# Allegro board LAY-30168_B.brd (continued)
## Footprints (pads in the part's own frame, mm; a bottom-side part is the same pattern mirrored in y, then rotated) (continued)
HDR205_50_TH
  rect 1.016x1.016 hole 0.66: 1(0,0)
  round 1.016 hole 0.66: 2(0,1.27) 3(1.27,0) 4(1.27,1.27) 5(2.54,0) 6(2.54,1.27) 7(3.81,0) 8(3.81,1.27) 9(5.08,0) 10(5.08,1.27)
HDR_2X10M_100_TH
  rect 1.778x1.778 hole 1.143: 1(0,0)
  round 1.778 hole 1.143: 2(2.54,0) 3(0,-2.54) 4(2.54,-2.54) 5(0,-5.08) 6(2.54,-5.08) 7(0,-7.62) 8(2.54,-7.62) 9(0,-10.16) 10(2.54,-10.16) 11(0,-12.7) 12(2.54,-12.7) 13(0,-15.24) 14(2.54,-15.24) 15(0,-17.78) 16(2.54,-17.78) 17(0,-20.32) 18(2.54,-20.32) 19(0,-22.86) 20(2.54,-22.86)
IND4_4P7X3P4_SMT
  rect 1.372x0.914 smd: 1(-2.275,1.25) 2(-2.275,-1.25) 3(2.275,-1.25) 4(2.275,1.25)
IND4_CHOKE_0805
  rect 0.914x0.406 smd: 1(-0.85,-0.4) 2(0.85,-0.4) 3(0.85,0.4) 4(-0.85,0.4)
IND_1608
  rect 0.61x0.813 smd: 1(-0.7,0) 2(0.7,0)
IND_4020
  rect 1.118x3.708 smd: 1(-1.5,0) 2(1.5,0)
IND_VLS4012E
  rect 1.549x4.013 smd: 1(-1.475,0) 2(1.475,0)
LED_0603
  rect 0.838x0.787 smd: A(-0.775,0) C(0.775,0)
LED_DUAL_3025MM_SM
  rect 1.702x1.118 smd: 1(-1.35,-0.85) 2(1.35,-0.85) 3(-1.35,0.85) 4(1.35,0.85)
MIC_WM-63PR
  rect 1.27x1.27 hole 0.762: 1(0,0)
  round 1.27 hole 0.762: 2(0,1.9)
MICROPAK_6P
  rect 0.305x0.508 smd: 1(-0.508,-0.381) 2(0,-0.381) 3(0.508,-0.381) 4(0.508,0.381) 5(0,0.381) 6(-0.508,0.381)
MLP6_2X2MM_SLUG
  rect 0.483x0.406 smd: 1(-0.913,0.65) 2(-0.913,0) 3(-0.913,-0.65) 4(0.913,-0.65) 5(0.913,0) 6(0.913,0.65)
  rect 1.016x0.991 smd: 7(0,0.3)
  rect 0.66x0.406 smd: 8(0,-0.65)
MODULE_TOUCH_PANEL_46P
  rect 2.007x2.997 smd: (-35.23,11.683) (-12.65,11.683) (23.91,11.481) (29.49,11.481)
  rect 0.279x1.245 smd: A1(-33.69,14.008) A2(-33.19,14.008) A3(-32.69,14.008) A4(-32.19,14.008) A5(-31.69,14.008) A6(-31.19,14.008) A7(-30.69,14.008) A8(-30.19,14.008) A9(-29.69,14.008) A10(-29.19,14.008) A11(-28.69,14.008) A12(-28.19,14.008) A13(-27.69,14.008) A14(-27.19,14.008) A15(-26.69,14.008) A16(-26.19,14.008) A17(-25.69,14.008) A18(-25.19,14.008) A19(-24.69,14.008) A20(-24.19,14.008) A21(-23.69,14.008) A22(-23.19,14.008) A23(-22.69,14.008) A24(-22.19,14.008) A25(-21.69,14.008) A26(-21.19,14.008) A27(-20.69,14.008) A28(-20.19,14.008) A29(-19.69,14.008) A30(-19.19,14.008) A31(-18.69,14.008) A32(-18.19,14.008) A33(-17.69,14.008) A34(-17.19,14.008) A35(-16.69,14.008) A36(-16.19,14.008) A37(-15.69,14.008) A38(-15.19,14.008) A39(-14.69,14.008) A40(-14.19,14.008)
  rect 0.305x1.245 smd: B1(25.45,13.806) B2(25.95,13.806) B3(26.45,13.806) B4(26.95,13.806) B5(27.45,13.806) B6(27.95,13.806)
PBGA24_1_6X8MM
  round 0.33 smd: A2(-1,2) A3(0,2) A4(1,2) A5(2,2) B1(-2,1) B2(-1,1) B3(0,1) B4(1,1) B5(2,1) C1(-2,0) C2(-1,0) C3(0,0) C4(1,0) C5(2,0) D1(-2,-1) D2(-1,-1) D3(0,-1) D4(1,-1) D5(2,-1) E1(-2,-2) E2(-1,-2) E3(0,-2) E4(1,-2) E5(2,-2)
QFN5X3_0P5_3X3
  rect 0.813x0.305 smd: 1(-1.275,1) 2(-1.275,0.5) 3(-1.275,0) 4(-1.275,-0.5) 5(-1.275,-1) 9(1.275,-1) 10(1.275,-0.5) 11(1.275,0) 12(1.275,0.5) 13(1.275,1)
  rect 0.305x0.813 smd: 6(-0.5,-1.275) 7(0,-1.275) 8(0.5,-1.275) 14(0.5,1.275) 15(0,1.275) 16(-0.5,1.275)
QFN32_0P5_EP3P3
  oval 0.864x0.279 smd: 1(-2.45,1.75) 8(-2.45,-1.75) 17(2.45,-1.75) 24(2.45,1.75)
  rect 0.864x0.279 smd: 2(-2.45,1.25) 3(-2.45,0.75) 4(-2.45,0.25) 5(-2.45,-0.25) 6(-2.45,-0.75) 7(-2.45,-1.25) 18(2.45,-1.25) 19(2.45,-0.75) 20(2.45,-0.25) 21(2.45,0.25) 22(2.45,0.75) 23(2.45,1.25)
  oval 0.279x0.864 smd: 9(-1.75,-2.45) 16(1.75,-2.45) 25(1.75,2.45) 32(-1.75,2.45)
  rect 0.279x0.864 smd: 10(-1.25,-2.45) 11(-0.75,-2.45) 12(-0.25,-2.45) 13(0.25,-2.45) 14(0.75,-2.45) 15(1.25,-2.45) 26(1.25,2.45) 27(0.75,2.45) 28(0.25,2.45) 29(-0.25,2.45) 30(-0.75,2.45) 31(-1.25,2.45)
  rect 3.302x3.302 smd: 33(0,0)
QFN32_S142EP
  custom 0.07x0.07 smd: 1(-2.4,1.751) 2(-2.4,1.251) 3(-2.4,0.751) 4(-2.4,0.25) 5(-2.4,-0.25) 6(-2.4,-0.751) 7(-2.4,-1.251) 8(-2.4,-1.751) 9(-1.751,-2.4) 10(-1.251,-2.4) 11(-0.751,-2.4) 12(-0.25,-2.4) 13(0.25,-2.4) 14(0.751,-2.4) 15(1.251,-2.4) 16(1.751,-2.4) 17(2.4,-1.751) 18(2.4,-1.251) 19(2.4,-0.751) 20(2.4,-0.25) 21(2.4,0.25) 22(2.4,0.751) 23(2.4,1.251) 24(2.4,1.751) 25(1.751,2.4) 26(1.251,2.4) 27(0.751,2.4) 28(0.25,2.4) 29(-0.25,2.4) 30(-0.751,2.4) 31(-1.251,2.4) 32(-1.751,2.4)
  rect 3.607x3.607 smd: 33(0,0)
RC0402_25
  round 0.635 smd: 1(-0.508,0) 2(0.508,0)
RC0603_OV
  oval 0.889x1.143 smd: 1(-0.762,0) 2(0.762,0)
RC0805_OV
  oval 0.889x1.524 smd: 1(-0.965,0) 2(0.965,0)
SC-70
  rect 0.381x0.813 smd: 1(-0.66,-1.079) 2(0,-1.079) 3(0.66,-1.079) 4(0.66,1.079) 5(-0.66,1.079)
SC_75
  rect 0.483x0.635 smd: 1(-0.5,-0.647) 2(0.5,-0.647) 3(0,0.647)
SLP1616P6
  rect 0.305x0.635 smd: 1(-0.5,-0.76) 2(0,-0.76) 3(0.5,-0.76) 4(0.5,0.76) 5(0,0.76) 6(-0.5,0.76)
  rect 1.295x0.457 smd: 7(0,0)
SO8-25X75-200
  oval 0.635x1.905 smd: 1(-1.905,-3.67) 2(-0.635,-3.67) 3(0.635,-3.67) 4(1.905,-3.67) 5(1.905,3.67) 6(0.635,3.67) 7(-0.635,3.67) 8(-1.905,3.67)
SO8_1P27_4X5
  rect 1.6x0.61 smd: 1(-2.7,1.905) 2(-2.7,0.635) 3(-2.7,-0.635) 4(-2.7,-1.905) 5(2.7,-1.905) 6(2.7,-0.635) 7(2.7,0.635) 8(2.7,1.905)
SOD523
  rect 0.61x0.813 smd: A(0.85,0) C(-0.85,0)
SOD-123
  rect 1.321x1.219 smd: A(-1.626,0) C(1.626,0)
SOD_523_1P4
  rect 0.406x0.406 smd: A(0.7,0) C(-0.7,0)
SOT23-3-1P95
  rect 0.584x1.194 smd: 1(-0.953,-1.25) 2(0.953,-1.25) 3(0,1.25)
SOT23-5_A
  rect 1.016x0.762 smd: 1(-1.3,0.95) 2(-1.3,0) 3(-1.3,-0.95) 4(1.3,-0.95) 5(1.3,0.95)
SOT23_6_B
  rect 0.61x1.194 smd: 1(-0.95,-1.2) 2(0,-1.2) 3(0.95,-1.2) 4(0.95,1.2) 5(0,1.2) 6(-0.95,1.2)
SOT23_A
  rect 0.787x0.889 smd: 1(-0.94,-1.003) 2(0.94,-1.003) 3(0,1.003)
SOT23_S6
  rect 1.27x0.635 smd: 1(-1.219,0.94) 2(-1.219,0) 3(-1.219,-0.94) 4(1.219,-0.94) 5(1.219,0) 6(1.219,0.94)
SOT143B
  rect 0.991x0.61 smd: 1(-0.75,-1)
  rect 0.508x0.61 smd: 2(0.95,-1) 3(0.95,1) 4(-0.95,1)
SOT323_3
  rect 0.406x0.991 smd: 1(0.65,-1.06) 2(-0.65,-1.06) 3(0,1.06)
SOT-23
  rect 1.016x1.397 smd: 1(-0.95,-1.1) 2(0.95,-1.1) 3(0,1.1)
SOT-363_0P65_SMT
  rect 0.762x0.381 smd: 1(-1.085,0.65) 2(-1.085,0) 3(-1.085,-0.65) 4(1.085,-0.65) 5(1.085,0) 6(1.085,0.65)
SOT_143
  rect 1.219x1.397 smd: 1(-0.75,-1.1)
  rect 1.016x1.397 smd: 2(0.95,-1.1) 3(0.95,1.1) 4(-0.95,1.1)
SPACER_139T
  round 5.588 hole 3.531: 1(0,0)
SSOP8_DCU
  rect 0.279x1.219 smd: 1(-0.75,-1.499) 2(-0.25,-1.499) 3(0.25,-1.499) 4(0.75,-1.499) 5(0.75,1.499) 6(0.25,1.499) 7(-0.25,1.499) 8(-0.75,1.499)
SW4_PB_ESW_SM_P177
  rect 1.397x2.794 smd: 1(2.248,4.547) 2(2.248,-4.547) 3(-2.248,4.547) 4(-2.248,-4.547)
SW6_DPDT_11X6MM
  rect 1.143x1.143 hole 0.711: 1(0,0)
  round 1.143 hole 0.711: 2(2,0) 3(4,0) 4(0,-2.5) 5(2,-2.5) 6(4,-2.5)
TESTPOINT_35MIL
  round 0.889 smd: 1(0,0)
TP_TH_063
  round 2.311 hole 1.6: 1(0,0)
TPAD_030
  round 0.762 smd: 1(0,0)
TSOT23_8_0P65_2X1
  rect 1.219x0.432 smd: 1(-1.31,0.975) 2(-1.31,0.325) 3(-1.31,-0.325) 4(-1.31,-0.975) 5(1.31,-0.975) 6(1.31,-0.325) 7(1.31,0.325) 8(1.31,0.975)
TSSOP8_A
  rect 1.448x0.457 smd: 1(-2.15,0.975) 2(-2.15,0.325) 3(-2.15,-0.325) 4(-2.15,-0.975) 5(2.15,-0.975) 6(2.15,-0.325) 7(2.15,0.325) 8(2.15,0.975)
VFBGA54_8X8
  round 0.356 smd: A1(-3.2,3.2) A2(-2.4,3.2) A3(-1.6,3.2) A7(1.6,3.2) A8(2.4,3.2) A9(3.2,3.2) B1(-3.2,2.4) B2(-2.4,2.4) B3(-1.6,2.4) B7(1.6,2.4) B8(2.4,2.4) B9(3.2,2.4) C1(-3.2,1.6) C2(-2.4,1.6) C3(-1.6,1.6) C7(1.6,1.6) C8(2.4,1.6) C9(3.2,1.6) D1(-3.2,0.8) D2(-2.4,0.8) D3(-1.6,0.8) D7(1.6,0.8) D8(2.4,0.8) D9(3.2,0.8) E1(-3.2,0) E2(-2.4,0) E3(-1.6,0) E7(1.6,0) E8(2.4,0) E9(3.2,0) F1(-3.2,-0.8) F2(-2.4,-0.8) F3(-1.6,-0.8) F7(1.6,-0.8) F8(2.4,-0.8) F9(3.2,-0.8) G1(-3.2,-1.6) G2(-2.4,-1.6) G3(-1.6,-1.6) G7(1.6,-1.6) G8(2.4,-1.6) G9(3.2,-1.6) H1(-3.2,-2.4) H2(-2.4,-2.4) H3(-1.6,-2.4) H7(1.6,-2.4) H8(2.4,-2.4) H9(3.2,-2.4) J1(-3.2,-3.2) J2(-2.4,-3.2) J3(-1.6,-3.2) J7(1.6,-3.2) J8(2.4,-3.2) J9(3.2,-3.2)
WLCSP4_0P4_0P8X0P8_SMDP
  round 0.254 smd: A1(-0.2,0.2) A2(0.2,0.2) B1(-0.2,-0.2) B2(0.2,-0.2)
WLCSP12_0P4_1P38X1P68MM_SMDP
  round 0.254 smd: A1(-0.4,0.6) A2(0,0.6) A3(0.4,0.6) B1(-0.4,0.2) B2(0,0.2) B3(0.4,0.2) C1(-0.4,-0.2) C2(0,-0.2) C3(0.4,-0.2) D1(-0.4,-0.6) D2(0,-0.6) D3(0.4,-0.6)
XFMR6_6P6X6P2
  rect 1.194x1.295 smd: (-2.73,0) (2.73,0) 1(-2.73,2.54) 3(-2.73,-2.54) 4(2.73,-2.54) 6(2.73,2.54)
XQFN8_1P45X1P25MM
  rect 0.787x0.203 smd: 1(-0.75,0)
  rect 0.203x0.711 smd: 2(-0.4,-0.65) 3(0,-0.65) 4(0.4,-0.65) 6(0.4,0.65) 7(0,0.65) 8(-0.4,0.65)
  rect 0.711x0.203 smd: 5(0.75,0)
XTAL2-3P2X1P5-SM
  rect 1.092x1.905 smd: 1(-1.25,0) 2(1.25,0)
XTL2_11P6X4P85_SM
  rect 5.588x2.032 smd: 1(-4.75,0) 2(4.75,0)
XTLOSC4_3P2X2P5MM_SM
  rect 1.397x1.194 smd: 1(-1.1,-0.8) 2(1.1,-0.8) 3(1.1,0.8) 4(-1.1,0.8)

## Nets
5V_SDA_PSW: C241.1 R352.1 U31.C2(VBUS1) U31.D1(VBUS2) U31.D2(VBUS3)
5V_SYS: C50.1 C51.1 C61.1 C62.1 D14.A J1.2(B1) J1.4(B2) J1.6(B3) J1.8(B4) J25.8 R7.1 R33.1 R64.1 R85.1 R95.1 R328.1 R336.1 U4.1(IN) U4.3(S\H\D\N\) U6.1(IN)
5V_USB_HS: C84.1 C97.1 C239.1 L7.2 U1.P6(USB_OTG2_VBUS) U35.C2(VBUS1) U35.D1(VBUS2) U35.D2(VBUS3)
5V_USB_OTG: C79.1 C93.1 C240.1 J1.3(A2) L4.2 U1.N6(USB_OTG1_VBUS) U34.C2(VBUS1) U34.D1(VBUS2) U34.D2(VBUS3)
GND: C1.2 C2.2 C3.2 C4.2 C6.2 C7.2 C8.2 C9.2 C10.2 C11.2 C12.2 C13.2 C14.2 C15.2 C16.2 C17.2 C18.2 C19.2 C20.2 C21.2 C22.2 C23.2 C24.2 C25.2 C26.2 C27.2 C29.2 C30.2 C31.2 C32.2 C33.2 C34.2 C35.2 C36.2 C37.2 C39.2 C40.2 C41.2 C42.2 C43.2 C44.2 C45.2 C46.2 C47.2 C48.2 C49.2 C50.2 C51.2 C52.2 C53.2 C54.2 C55.2 C56.2 C57.2 C58.2 C59.2 C61.2 C62.2 C63.2 C64.2 C65.2 C66.2 C67.2 C68.2 C69.2 C70.2 C71.2 C72.2 C73.2 C74.2 C75.2 C76.2 C77.2 C78.2 C79.2 C80.2 C81.2 C82.2 C83.2 C84.2 C85.2 C86.2 C87.2 C88.2 C89.2 C90.2 C91.2 C92.2 C93.2 C97.2 C98.2 C99.2 C100.2 C101.1 C102.2 C103.2 C104.2 C105.2 C106.2 C107.2 C108.2 C109.2 C110.2 C111.2 C112.2 C113.2 C114.1 C115.2 C116.2 C117.2 C118.1 C119.2 C120.2 C121.1 C127.2 C128.2 C129.2 C130.2 C133.2 C134.1 C135.1 C136.2 C137.2 C138.2 C140.2 C141.2 C142.2 C143.2 C144.2 C145.2 C146.2 C147.2 C148.2 C149.2 C150.2 C160.2 C161.2 C162.2 C163.2 C164.2 C165.2 C166.2 C167.2 C168.2 C169.2 C170.2 C171.2 C184.2 C185.2 C186.2 C187.2 C188.2 C189.2 C190.2 C191.2 C192.2 C193.2 C194.2 C195.2 C196.2 C197.2 C198.2 C199.2 C200.2 C201.2 C202.2 C203.2 C204.2 C205.2 C206.2 C207.2 C208.2 C209.2 C210.2 C211.2 C212.2 C213.2 C214.2 C215.2 C216.2 C217.2 C218.2 C219.2 C220.2 C221.2 C222.2 C223.2 C229.2 C234.2 C235.2 C236.2 C237.2 C238.2 C239.2 C240.2 C241.2 C242.2 C243.2 C244.2 C245.2 C246.2 C247.2 C248.2 C249.2 C252.2 C254.2 C255.2 C257.2 C258.2 C259.2 C260.2 C261.2 C262.2 C263.2 C264.2 C265.2 C266.2 C267.2 C268.2 C270.2 C272.2 C273.2 C274.2 C275.2 C276.2 C277.2 C278.2 D1.A(ANODE) D3.4(CATHODE2) D11.3(ANODES) D20.C(CATHODE) H1.1(NC_1) H2.1(NC_1) H3.1(NC_1) H4.1(NC_1) J1.9(A5) J1.10(B5) J2.2 J2.3 J6.1 J8.A3(GND2) J8.A5(R0) J8.A6(R1) J8.A7(R2) J8.A13(G0) J8.A14(G1) J8.A21(B0) J8.A22(B1) J8.A23(B2) J8.A29(GND3) J8.A36(GND4) J8.B6(GND1) J9.5(P5) J10.5(P5) J11.2 J12.1 J19.10(CHS_GND) J21.4 J21.6 J21.8 J21.10 J21.12 J21.14 J21.16 J21.18 J21.20 J24.7 J25.6 J25.7 J34.3(A2) J34.5(A3) J35.1 J35.2 J35.10 J39.6(VSS) J39.SH1(GND1) J39.SH2(GND2) J39.SH3(GND3) J39.SH4(GND4) J41.5(P5) J42.1 L6.2 L9.2 L14.1 L17.2 L22.2 Q1.3(G) Q4.2(SOURCE) Q15.1(SOURCE) R11.2 R30.2 R31.2 R39.2 R45.2 R52.2 R54.2 R65.2 R66.2 R97.1 R103.2 R113.1 R116.2 R117.2 R125.2 R133.2 R135.2 R136.2 R137.2 R140.2 R141.2 R143.2 R146.2 R148.2 R149.2 R150.2 R152.2 R172.2 R173.2 R180.2 R181.2 R182.2 R185.2 R214.2 R247.1 R248.1 R249.1 R250.1 R251.1 R252.1 R253.1 R254.1 R255.1 R256.1 R257.1 R258.1 R259.1 R260.1 R266.2 R267.2 R269.2 R303.2 R304.2 R314.2 R326.2 R333.2 R335.2 R342.2 R348.2 R351.2 R377.2 R380.1 R387.1 R389.2 R391.2 R414.2 SW1.3(NO1) SW1.6(NO2) SW2.1(A1) SW2.2(A2) SW3.1(A1) SW3.2(A2) SW8.1(A1) SW8.2(A2) SW9.1(A1) SW9.2(A2) T1.4 TP2.1 TP3.1 TP4.1 TP5.1 TVS1.1(A1) TVS2.1(A1) TVS3.1(A1) TVS4.1(A1) TVS5.1(A1) U1.A1(VSS1) U1.A14(VSS2) U1.B5(VSS3) U1.B10(VSS4) U1.E2(VSS5) U1.E13(VSS6) U1.G7(VSS7) U1.G8(VSS8) U1.H7(VSS9) U1.H8(VSS10) U1.J7(VSS11) U1.J8(VSS12) U1.K2(VSS13) U1.K6(TEST_MODE) U1.K9(NGND_KEL0) U1.K13(VSS14) U1.L9(VSS15) U1.N1(DCDC_GND_1) U1.N2(DCDC_GND_2) U1.N5(VSS16) U1.N8(VSS17) U1.P1(VSS18) U1.P14(VSS19) U2.1(GND) U3.4(PGND) U3.6(AGND) U4.2(GND) U5.1(GND) U6.2(GND) U7.1(GND) U8.2(GND) U9.7(GND) U11.7(GND) U12.2(GND) U13.9(DGND) U13.20(SPKGND2) U13.24(SPKGND1) U13.28(AGND) U13.33(GND_PADDLE) U14.2(GND) U15.3(GND) U16.1(GND) U16.33(PADDLE) U17.2(A2) U19.B3(VSS) U19.C1(VSSQ1) U19.E5(VSSQ2) U20.A1(VSS1) U20.A3(VSSQ1) U20.B7(VSSQ2) U20.C3(VSSQ3) U20.D7(VSSQ4) U20.E3(VSS2) U20.J1(VSS3) U31.B3(GND1) U31.C3(GND2) U31.D3(GND3) U32.3(RSVD1) U32.5(GND1) U32.12(GND2) U32.13(RSVD2) U33.4(GND) U34.B3(GND1) U34.C3(GND2) U34.D3(GND3) U35.B3(GND1) U35.C3(GND2) U35.D3(GND3) U37.B2(GND) U38.C2(VSSA) U38.C8(VSS1) U38.D3(USB0_VSSA_TERM) U38.D4(VSS2) U38.D5(VSS3) U38.F2(USB0_VSSA_REF) U38.G8(VSS4) U38.J3(VSS5) U38.J6(VSS6) U39.1(GND) U40.2(GND) U44.4(GND) U45.2(GND) U46.2(GND) U48.4(GND) U49.2(GND) U49.5(DIR) Y1.2(GND1) Y1.4(GND2)
P3V3_SDA: C186.1 C255.1 C260.1 C262.1 C263.1 C264.1 C265.1 C266.1 C267.1 C270.1 J34.1(A1) L24.1 R213.1 R215.1 R378.1 R381.1 R382.1 R383.1 R388.2 R390.2 R394.1 R402.2 R413.1 R418.2 R423.1 U38.B2(VDDA) U38.C5(VBAT) U38.D1(USB0_VDDA3V3_DRIVER) U38.D2(USB0_VDDA3V3) U38.F10(VDDIO1) U38.K5(VDDIO2) U40.5(OUT) U44.1(VCCA) U45.3(VCCA) U46.1(VCCA) U48.1(VCCA) U49.1(VCCA)
P5V0_SDA_USB_CONN_VBUS: J41.1(P1) L23.1 U39.4(VCC)
P5V_SDA: C184.1 C185.1 C257.1 C259.1 L23.2 R212.1 R353.1 R379.1 U31.B1(VINT1) U31.B2(VINT2) U31.C1(VINT3) U40.1(IN) U40.3(S\H\D\N\)
P5V_SDA_S: J1.5(A3) R352.2 R353.2
VDD_COIN_3V: D5.A J6.2 R16.1
VDD_HIGH_IN_3V3: C229.1 J4.1 R14.1 R310.2 R311.2
VDD_HIGH_IN_MCU: C15.1 C16.1 J4.2 R14.2 U1.P12(VDD_HIGH_IN)
VDD_SNVS_3V3: C49.1 C59.1 D4.A R34.2 R354.2 U5.4(VCC)
VDD_SNVS_IN: C23.1 J5.2 R15.2 R21.1 U1.M9(VDD_SNVS_IN)
VDD_SOC_IN: C8.1 C9.1 C10.1 C11.1 C12.1 C13.1 C14.1 C17.1 C18.1 C19.1 C20.1 J36.1 R13.1 U1.F6(VDD_SOC_IN_1) U1.F7(VDD_SOC_IN_2) U1.F8(VDD_SOC_IN_3) U1.F9(VDD_SOC_IN_4) U1.G6(VDD_SOC_IN_5) U1.G9(VDD_SOC_IN_6) U1.H6(VDD_SOC_IN_7) U1.H9(VDD_SOC_IN_8) U1.J5(DCDC_SENSE) U1.J9(VDD_SOC_IN_9)
VDD_USB_3V: C82.1 C83.1 U1.K8(VDD_USB_CAP)
VDDA_ADC_3P3_MCU: C6.1 C7.1 J3.2 R12.2 U1.N14(VDDA_ADC_3P3)
VDDA_ADC_3V3: C57.1 J3.1 R12.1 R44.2
AUD_INT: R96.1 R222.2 R275.1 R287.2 U1.H13(GPIO_AD_B1_08)
BACKLIGHT_CTL: R314.1 R344.1 U1.B14(GPIO_B1_15) U8.4(CE)
BL+: J8.A2(VBL+) R63.2
BL-: C91.1 J8.A1(VBL-) R65.1 R66.1 U8.3(FB)
BOOT0_LED: R388.1 R392.1 U38.K2(P1_1/GPIO0[8]/CTOUT_7/EMC_A6/SG)
BOOT1: R389.1 U38.K1(P1_2/GPIO0[9]/CTOUT_6/EMC_A7/SG)
BOOT2: R390.1 U38.C6(P2_8/SGPIO15/CTOUT_0/U3_DIR/EMC)
BOOT3: R391.1 U38.B10(P2_9/GPIO1[10]/CTOUT_3/U3_BAUD/)
BOOT_FLASH: J42.2 U38.C10(P2_7/GPIO0[7]/CTOUT_1/U3_UCLK/E)
CAN1_H: C101.2 D11.2(CATHODE2) FL1.1 J11.1 R87.2 R88.1
CAN1_L: C103.1 D11.1(CATHODE1) FL1.2 J11.3 R89.2 R91.2
CAN2_RX: U1.L10(GPIO_AD_B0_15) U12.4(RXD)
CAN2_TX: U1.H14(GPIO_AD_B0_14) U12.1(TXD)
CAN_STBY: R92.1 R169.1 R260.2 SW7.3(A3) U1.G14(GPIO_AD_B0_05)
CAN_VIO_3V3: C100.1 R86.1 R90.1 U12.5(VIO)
CSI_1V8: C247.1 J35.15 L20.2
CSI_D2: J35.6 R229.1
CSI_D3: J35.4 R228.1
CSI_D4: J35.3 R227.1
CSI_D5: J35.5 R226.1
CSI_D6: J35.7 R225.1
CSI_D7: J35.9 R224.1
CSI_D8: J35.11 R223.1
CSI_D9: J35.13 R222.1
CSI_HSYNC: J35.16 R221.1
CSI_MCLK: J35.12 R218.1
CSI_PIXCLK: J35.8 R217.1
CSI_PWDN: D17.C J22.7 J38.2 U1.L11(GPIO_AD_B1_02)
CSI_VSYNC: J35.18 R220.1
DC_5V_IN: C4.1 J2.1 Q1.1(D1) Q1.2(D2) Q1.5(D5) Q1.6(D6) Q1.7(D7) R1.1 R2.1 R6.1 TP1.1(PIN1)
DCDC_3V3: C69.1 C70.1 C71.1 C72.1 C73.1 C74.1 C75.1 C193.1 C194.1 C195.1 C196.1 C197.1 C198.1 C199.1 C200.1 C201.1 C202.1 C203.1 C204.1 C205.1 C206.1 C207.1 C208.1 C209.1 C210.1 C211.1 C212.1 C213.1 C214.1 C215.1 C216.1 C217.1 C218.1 C219.1 C220.1 C221.1 C222.1 C246.1 C249.1 C252.1 C268.1 C275.1 C276.1 C277.1 C278.1 D12.A J7.1 J13.2 J21.2 J24.8 J25.2 J25.4 J35.14 L18.1 L19.2 Q6.2(SOURCE) R24.1 R25.1 R27.1 R44.1 R48.1 R55.1 R57.1 R86.2 R93.1 R130.1 R174.1 R176.1 R177.1 R178.1 R179.1 R219.1 R230.1 R232.1 R234.1 R235.1 R236.1 R237.1 R238.1 R239.1 R240.1 R241.1 R242.1 R243.1 R244.1 R245.1 R246.1 R284.1 R293.1 R301.1 R311.1 R316.1 R324.1 R325.1 R332.1 R346.1 R349.1 R350.1 R354.1 R372.1 R393.1 R401.1 R411.1 R412.1 R419.2 R422.2 U1.E6(NVCC_EMC_1) U1.E9(NVCC_GPIO_1) U1.F5(NVCC_EMC_2) U1.F10(NVCC_GPIO_2) U1.J10(NVCC_GPIO_3) U37.A1(VIN) U44.8(VCCB) U45.7(VCCB) U46.6(VCCB) U48.8(VCCB) U49.6(VCCB)
DCDC_3V3_PG: C55.1 C56.1 TP8.1(TP) U3.1(PG) U6.3(S\H\D\N\)
DCDC_OUT: C36.1 C37.1 J36.2 L1.1 R13.2
ENET_3V3: C148.1 J19.1(LED_Y1) J19.12(LED_G12) L13.1 R126.1 R127.1 R128.1 R129.1 R130.2 R131.1 R132.1 R134.2 R138.2 R139.2 R142.2 R144.2 R145.2 R147.2 R151.2 R309.1 R322.2 U16.17(VDDIO)
ENET_B-CAST-OFF: R151.1 TP12.1(TP) U16.19(REF_CLK/B-CAST_OFF)
ENET_CONFIG0: R140.1 R142.1 U16.28(CONFIG0)
ENET_CONFIG1: R143.1 R144.1 U16.29(CONFIG1)
ENET_CRS_DV: R141.1 R145.1 U1.C12(GPIO_B1_06) U16.18(CRS_DV/CONFIG2)
ENET_INT: J21.13 J22.6 J50.2 R152.1 R262.2 R263.2 R309.2 R428.2 U1.G13(GPIO_AD_B0_10) U16.21(INTRP/N\A\N\D\_\T\R\E\E\)
ENET_LED0/NWAYEN: J19.2(LED_Y2) R148.1 U16.30(LED0/NWAYEN)
ENET_LED1/SPEED: J19.11(LED_G11) R149.1 U16.31(LED1/SPEED)
ENET_MDC: R132.2 U1.A7(GPIO_EMC_40) U16.12(MDC)
ENET_MDIO: R131.2 U1.C7(GPIO_EMC_41) U16.11(MDIO)
ENET_PHYAD0: R134.1 R137.1 U16.13(PHYAD0)
ENET_PHYAD1: R135.1 R138.1 U16.14(PHYAD1)
ENET_RST: D18.C(CATHODE) J21.5 J22.5 J49.2 R177.2 R323.1 U1.F14(GPIO_AD_B0_09)
ENET_RXD0: R150.1 U1.E12(GPIO_B1_04) U16.16(RXD0/DUPLEX)
ENET_RXD1: R136.1 R139.1 U1.D12(GPIO_B1_05) U16.15(RXD1/PHYAD2)
ENET_RXER: R146.1 R147.1 U1.C13(GPIO_B1_11) U16.20(RXER/ISO)
ENET_RXM: C147.1 J19.8(RD-) R129.2 U16.4(RXM) U17.3(A3)
ENET_RXP: C146.1 J19.7(RD+) R128.2 U16.5(RXP) U17.1(A1)
ENET_TX_CLK: TP25.1(TP) U1.B13(GPIO_B1_10) U16.9(XI)
ENET_TXD0: TP26.1(TP) U1.B12(GPIO_B1_07) U16.24(TXD0)
ENET_TXD1: U1.A12(GPIO_B1_08) U16.25(TXD1)
ENET_TXEN: U1.A13(GPIO_B1_09) U16.23(TXEN)
ENET_TXM: C145.1 J19.4(TD-) R127.2 U16.6(TXM) U17.4(A4)
ENET_TXP: C144.1 J19.3(TD+) R126.2 U16.7(TXP) U17.6(A6)
FLASH_VCC: C80.1 C81.1 C162.1 C163.1 C191.1 C192.1 R49.2 R168.1 R170.1 R171.1 R294.1 R301.2 R358.1 R359.1 R360.1 U1.K5(NVCC_SD1) U19.B4(VCC) U19.D1(VCCQ1) U19.E4(VCCQ2) U33.8(VCC)
FLEXSPI_CLK: R154.1 R361.1 U1.L4(GPIO_SD_B1_07)
FLEXSPI_CLK_B: U1.P2(GPIO_SD_B1_04) U19.B1(C\K\)
FLEXSPI_D0_A: R155.2 R362.1 U1.P3(GPIO_SD_B1_08)
FLEXSPI_D0_B: U1.M4(GPIO_SD_B1_03) U19.D5(DQ4)
FLEXSPI_D1_A: R156.2 R363.1 U1.N4(GPIO_SD_B1_09)
FLEXSPI_D1_B: U1.M3(GPIO_SD_B1_02) U19.E3(DQ5)
FLEXSPI_D2_A: R157.2 R364.1 U1.P4(GPIO_SD_B1_10)
FLEXSPI_D2_B: U1.M5(GPIO_SD_B1_01) U19.E2(DQ6)
FLEXSPI_D3_A: R158.2 R365.1 U1.P5(GPIO_SD_B1_11)
FLEXSPI_D3_B: U1.L5(GPIO_SD_B1_00) U19.E1(DQ7)
FLEXSPI_DQS: R366.1 U1.N3(GPIO_SD_B1_05)
FLEXSPI_SS0: R153.1 R356.1 R427.1 U1.L3(GPIO_SD_B1_06)
GPIO_AD_B0_00: R57.2 R341.1 U1.M14(GPIO_AD_B0_00)
GPIO_AD_B0_01: Q15.2(GATE) R55.2 R71.2 U1.H10(GPIO_AD_B0_01)
GPIO_AD_B0_02: J8.B2(RESET) J24.2 R329.1 U1.M11(GPIO_AD_B0_02)
GPIO_AD_B0_03: J24.1 R334.1 U1.G11(GPIO_AD_B0_03)
GPIO_AD_B0_04: R259.2 SW7.4(A4) U1.F11(GPIO_AD_B0_04)
GPIO_AD_B0_11: J8.B3(INT) J21.3 J22.3 R178.2 R261.2 R264.2 U1.G10(GPIO_AD_B0_11)
GPIO_AD_B1_00: J8.B4(SCL) J23.6 J35.20 R234.2 R270.2 R272.2 R277.2 U1.J11(GPIO_AD_B1_00) U13.17(SCLK)
GPIO_AD_B1_01: J8.B5(SDA) J23.5 J35.22 R232.2 R271.2 R273.2 R276.2 U1.K11(GPIO_AD_B1_01) U13.18(SDIN)
GPIO_AD_B1_03: D6.C J15.1 J22.8 U1.M12(GPIO_AD_B1_03)
GPIO_AD_B1_04: R217.2 R290.2 U1.L12(GPIO_AD_B1_04)
GPIO_AD_B1_05: R218.2 R291.2 U1.K12(GPIO_AD_B1_05)
GPIO_AD_B1_06: R220.2 R289.2 U1.J12(GPIO_AD_B1_06)
GPIO_AD_B1_07: R221.2 R288.2 U1.K10(GPIO_AD_B1_07)
GPIO_AD_B1_09: R102.1 R223.2 U1.M13(GPIO_AD_B1_09)
GPIO_AD_B1_10: R224.2 R285.2 U1.L13(GPIO_AD_B1_10)
GPIO_AD_B1_11: R225.2 R286.2 U1.J13(GPIO_AD_B1_11)
GPIO_AD_B1_12: R100.1 R226.2 U1.H12(GPIO_AD_B1_12)
GPIO_AD_B1_13: R101.1 R227.2 U1.H11(GPIO_AD_B1_13)
GPIO_AD_B1_14: R99.1 R228.2 U1.G12(GPIO_AD_B1_14)
GPIO_AD_B1_15: R98.1 R229.2 U1.J14(GPIO_AD_B1_15)
GPIO_B0_04: J8.A24(B3) R247.2 R325.2 U1.C8(GPIO_B0_04)
GPIO_B0_05: J8.A25(B4) R248.2 SW5.1(A1) U1.B8(GPIO_B0_05)
GPIO_B0_06: J8.A26(B5) R249.2 SW5.2(A2) U1.A8(GPIO_B0_06)
GPIO_B0_07: J8.A27(B6) R250.2 SW5.3(A3) U1.A9(GPIO_B0_07)
GPIO_B0_08: J8.A28(B7) R251.2 SW5.4(A4) U1.B9(GPIO_B0_08)
GPIO_B0_09: J8.A15(G2) R252.2 SW6.1(A1) U1.C9(GPIO_B0_09)
GPIO_B0_10: J8.A16(G3) R253.2 SW7.1(A1) U1.D9(GPIO_B0_10)
GPIO_B0_11: J8.A17(G4) R254.2 SW6.2(A2) U1.A10(GPIO_B0_11)
GPIO_B0_12: J8.A18(G5) R255.2 SW6.3(A3) U1.C10(GPIO_B0_12)
GPIO_B0_13: J8.A19(G6) R256.2 R428.1 SW7.2(A2) U1.D10(GPIO_B0_13)
GPIO_B0_14: J8.A20(G7) R257.2 SW6.4(A4) U1.E10(GPIO_B0_14)
GPIO_B0_15: J8.A8(R3) R258.2 R324.2 U1.E11(GPIO_B0_15)
GPIO_SD_B0_00: J39.3(CMD) R59.2 R280.2 U1.J4(GPIO_SD_B0_00)
GPIO_SD_B0_01_B: C245.1 J39.5(CLK) R281.2 R282.2
GPIO_SD_B0_02: J39.7(DAT0) R60.2 R279.2 U1.J1(GPIO_SD_B0_02)
GPIO_SD_B0_03: J39.8(DAT1) R278.2 U1.K1(GPIO_SD_B0_03)
HP_JD: J12.5 R94.2 R275.2 TVS3.2(A2) U13.7(RINPUT3/JD3)
HP_L: C230.1 U13.31(HP_L)
HP_MIC1N: C121.2 C123.1 U13.4(LINPUT1)
HP_MIC1P: C125.1 C127.1 U13.2(LINPUT3/JD2)
HP_R: C231.1 U13.29(HP_R)
JTAG_DACK: J21.19 R182.1
JTAG_DE: J21.17 R174.2
JTAG_MOD: R303.1 TP11.1(TP) U1.F13(GPIO_AD_B0_08)
JTAG_NSRST: D13.C J21.15 R175.2
JTAG_RESET: J44.2 U38.D10(P2_5/SGPIO14/CTIN_2/USB1_VBUS/A)
JTAG_RTCK: J21.11 R181.1
JTAG_TCK: J21.9 J48.2 R180.1 U1.F12(GPIO_AD_B0_07)
JTAG_TDI_L: U38.J10(P1_18/GPIO0[13]/U2_DIR/ENET_TXD) U48.3(2A)
JTAG_TDI_TGTMCU_BUF: J49.1 R417.2
JTAG_TDO_TGTMCU_BUF: J50.1 R422.1 U49.4(B)
JTAG_TMS: J21.7 J47.2 R176.2 U1.E14(GPIO_AD_B0_06)
JTAG_VREF: J21.1 R179.2
LCD_3V3: C85.1 C86.1 C87.1 C92.1 J8.A4(VDD2) J8.B1(VDD1) R62.2 R67.1
LCDIF_CLK: J8.A30(DCLK) U1.D7(GPIO_B0_00)
LCDIF_D12: J8.A9(R4) U1.A11(GPIO_B1_00)
LCDIF_D13: J8.A10(R5) U1.B11(GPIO_B1_01)
LCDIF_D14: J8.A11(R6) U1.C11(GPIO_B1_02)
LCDIF_D15: J8.A12(R7) U1.D11(GPIO_B1_03)
LCDIF_ENABLE: J8.A34(DE) U1.E7(GPIO_B0_01)
LCDIF_HSYNC: J8.A32(HSYNC) U1.E8(GPIO_B0_02)
LCDIF_VSYNC: J8.A33(VSYNC) U1.D8(GPIO_B0_03)
LDO_1V8: C67.1 C68.1 L20.1 R49.1 TP10.1(TP) U7.2(VOUT)
MAIN_MIC2N: C126.2 C130.1 U13.5(RINPUT1)
MAIN_MIC2P: C118.2 C122.2 U13.6(RINPUT2)
MCU_DCDC_IN: C31.1 C32.1 C33.1 C34.1 C35.1 J37.1 R32.1 R357.1 U1.K4(DCDC_IN_Q) U1.L1(DCDC_IN_1) U1.L2(DCDC_IN_2)
MCU_DCDC_IN_3V3: C223.1 J37.2 R25.2 R42.2 R357.2
MICBIAS: C112.1 R104.1 R105.1 U13.1(MICBIAS)
NVCC_SD: C63.1 C64.1 R46.1 R47.1 R59.1 R60.1 R61.1 TP9.1(TP) U6.5(OUT)
ONOFF: SW2.3(B1) SW2.4(B2) U1.M6(ONOFF)
OTG1_DN: L5.2 R68.2 U1.M8(USB_OTG1_DN)
OTG1_DP: L5.3 R69.2 U1.L8(USB_OTG1_DP)
OTG2_DN: L8.2 R83.2 U1.N7(USB_OTG2_DN)
OTG2_DP: L8.3 R84.2 U1.P7(USB_OTG2_DP)
PERI_3V3: Q6.3(DRAIN) R24.2 R62.1
PERI_PWREN: Q6.1(GATE) R31.1 U1.L7(PMIC_STBY_REQ)
PMIC_ON_REQ: R38.2 R355.1 U1.K7(PMIC_ON_REQ)
POR_B: C27.1 D7.C D13.A D21.C(CATHODE) J26.1 J43.3 R20.2 R21.2 R401.2 R410.2 U1.M7(P\O\R\) U44.7(B1)
POR_BUTTON: R43.1 R355.2 SW3.3(B1) SW3.4(B2)
POWER_EN: R216.1 U38.F7(P3_1/I2S0_TX_WS/I2S0_RX_WS/CAN0)
PWDN: D17.A J35.17 R219.2
SD0_VSELECT: Q9.2(GATE) R54.1 U1.C14(GPIO_B1_14)
SD1_CLK: C244.1 R282.1 U1.J3(GPIO_SD_B0_01)
SD1_D2: J39.1(DAT2) TP27.1(TP) U1.H2(GPIO_SD_B0_04)
SD1_D3: J39.2(CD/DAT3) R172.1 TP28.1(TP) U1.J2(GPIO_SD_B0_05)
SD_CD_SW: R320.2 U1.D13(GPIO_B1_12)
SDA_JTAG_TCLK: J34.4(B2) U38.H2(TCK/SWDCLK)
SDA_JTAG_TDI: J34.8(B4) U38.G3(TDI)
SDA_JTAG_TDO: J34.6(B3) U38.H3(TDO/SWO)
SDA_JTAG_TMS: J34.2(B1) R213.2 U38.C4(TMS/SWDIO)
SDA_RST: J34.10(B5) R423.2 U38.B4(T\R\S\T\)
SDA_RST_LED: D21.A(ANODE) R412.2
SDA_RST_TGTMCU_J_B: J44.1 R400.1 R410.1
SDA_USB_CONN_DM: J41.2(P2) R375.1 U39.2(I/O1)
SDA_USB_CONN_DP: J41.3(P3) R376.1 U39.3(I/O2)
SDA_USB_DM: R375.2 U38.E2(USB0_DM)
SDA_USB_DP: R376.2 U38.E1(USB0_DP)
SDA_USBSHIELD: J41.S1(SHLD1) J41.S2(SHLD2) J41.S3(SHLD3) J41.S4(SHLD4) L22.1
SDRAM_3V3: C164.1 C165.1 C166.1 C167.1 C168.1 C169.1 C170.1 C171.1 C243.1 L18.2 R184.1 U20.A7(VDDQ1) U20.A9(VDD1) U20.B3(VDDQ2) U20.C7(VDDQ3) U20.D3(VDDQ4) U20.E7(VDD2) U20.J9(VDD3)
SEMC_A0: U1.C2(GPIO_EMC_09) U20.H7(A0)
SEMC_A1: U1.G1(GPIO_EMC_10) U20.H8(A1)
SEMC_A2: U1.G3(GPIO_EMC_11) U20.J8(A2)
SEMC_A3: U1.H1(GPIO_EMC_12) U20.J7(A3)
SEMC_A4: U1.A6(GPIO_EMC_13) U20.J3(A4)
SEMC_A5: U1.B6(GPIO_EMC_14) U20.J2(A5)
SEMC_A6: U1.B1(GPIO_EMC_15) U20.H3(A6)
SEMC_A7: U1.A5(GPIO_EMC_16) U20.H2(A7)
SEMC_A8: U1.A4(GPIO_EMC_17) U20.H1(A8)
SEMC_A9: U1.B2(GPIO_EMC_18) U20.G3(A9)
SEMC_A10: U1.G2(GPIO_EMC_23) U20.H9(A10)
SEMC_A11: U1.B4(GPIO_EMC_19) U20.G2(A11)
SEMC_A12: U1.A3(GPIO_EMC_20) U20.G1(A12)
SEMC_BA0: U1.C1(GPIO_EMC_21) U20.G7(BA0)
SEMC_BA1: U1.F1(GPIO_EMC_22) U20.G8(BA1)
SEMC_CAS: U1.D3(GPIO_EMC_24) U20.F7(C\A\S\)
SEMC_CKE: R185.1 U1.A2(GPIO_EMC_27) U20.F3(CKE)
SEMC_CLK: R283.1 U1.B3(GPIO_EMC_26)
SEMC_CS0: R184.2 U1.E1(GPIO_EMC_29) U20.G9(C\S\)
SEMC_D0: U1.E3(GPIO_EMC_00) U20.A8(DQ0)
SEMC_D1: U1.F3(GPIO_EMC_01) U20.B9(DQ1)
SEMC_D2: U1.F4(GPIO_EMC_02) U20.B8(DQ2)
SEMC_D3: U1.G4(GPIO_EMC_03) U20.C9(DQ3)
SEMC_D4: U1.F2(GPIO_EMC_04) U20.C8(DQ4)
SEMC_D5: U1.G5(GPIO_EMC_05) U20.D9(DQ5)
SEMC_D6: U1.H5(GPIO_EMC_06) U20.D8(DQ6)
SEMC_D7: U1.H4(GPIO_EMC_07) U20.E9(DQ7)
SEMC_D8: U1.C6(GPIO_EMC_30) U20.E1(DQ8)
SEMC_D9: U1.C5(GPIO_EMC_31) U20.D2(DQ9)
SEMC_D10: U1.D5(GPIO_EMC_32) U20.D1(DQ10)
SEMC_D11: U1.C4(GPIO_EMC_33) U20.C2(DQ11)
SEMC_D12: U1.D4(GPIO_EMC_34) U20.C1(DQ12)
SEMC_D13: U1.E5(GPIO_EMC_35) U20.B2(DQ13)
SEMC_D14: U1.C3(GPIO_EMC_36) U20.B1(DQ14)
SEMC_D15: U1.E4(GPIO_EMC_37) U20.A2(DQ15)
SEMC_DM0: U1.H3(GPIO_EMC_08) U20.E8(LDQM)
SEMC_DM1: U1.D6(GPIO_EMC_38) U20.F1(UDQM)
SEMC_DQS: C76.1 U1.B7(GPIO_EMC_39)
SEMC_RAS: U1.D2(GPIO_EMC_25) U20.F8(R\A\S\)
SEMC_WE: U1.D1(GPIO_EMC_28) U20.F9(W\E\)
SENSOR_3V3: C187.1 C188.1 R261.1 R262.1 R265.1 R268.1 R270.1 R271.1 R284.2 U32.1(VDDIO) U32.14(VDD)
SPDIF_BUF: R122.1 R124.2 U15.4(Y)
SPDIF_COAX_OUT: J18.2 T2.1
SPDIF_GND_PRI: R123.2 R125.1 T2.4
SPDIF_OUT_PRI: C139.2 R123.1 T2.6
SPDIF_VCC: C133.1 C138.1 J13.1 U14.5(VCC) U15.1(OE) U15.5(VCC)
SPK_LN: R119.1 U13.23(SPK_LN)
SPK_LP: R121.1 U13.25(SPK_LP)
SPK_RN: R118.1 U13.19(SPK_RN)
SPK_RP: R120.1 U13.22(SPK_RP)
SW1_RST_B: C272.1 J43.2 SW9.3(B1) SW9.4(B2)
SWD_CLK_TGTMCU_BUF: J48.1 R416.2
SWD_DIO_TGTMCU_BUF: J47.1 R419.1 U46.4(B)
TC_SDA_USB_ID: J41.4(P4) U38.F1(USB0_ID)
TCK_SWCLK: U38.H10(P1_17/GPIO0[12]/U2_UCLK/ENET_MD) U48.2(1A)
TDO_SWO: U38.J8(P1_14/GPIO1[7]/U1_RXD/EMC_D7/T0) U49.3(A)
TMS_SWDIO: U38.K4(P1_6/GPIO1[9]/CTIN_5/E\M\C\_\W\) U46.3(A)
TMS_SWDIO_TXEN: R414.1 U38.J4(P1_5/GPIO1[8]/CTOUT_10/E\M\C\_\) U46.5(DIR)
TP_2102_A: TP29.1(PIN1) U44.3(A2)
TP_2102_B: TP30.1(PIN1) U44.6(B2)
UART1_RX_TGTMCU_BUF: J45.1 U45.8(B1)
UART1_RXD: J45.2 R411.2 U1.L14(GPIO_AD_B0_13)
UART1_TX_TGTMCU_BUF: J46.1 U45.1(B2)
UART1_TXD: J46.2 R393.2 U1.K14(GPIO_AD_B0_12)
UART_RXD_ISP: U38.G10(P2_0/SGPIO4/U0_TXD/EMC_A13/USB0) U45.5(A1)
UART_TXD_ISP: U38.G7(P2_1/SGPIO5/U0_RXD/EMC_A12/USB0) U45.4(A2)
USER_BUTTON: SW8.3(B1) SW8.4(B2) TP6.1(TP) U1.L6(WAKEUP)
VAUD_3V3: C104.1 C105.1 C106.1 C107.1 R93.2 R94.1 U13.8(DCVDD) U13.10(DBVDD) U13.32(AVDD)
VLDO_3V3: C52.1 C53.1 R34.1 R42.1 R305.1 R310.1 U4.5(OUT)
VSD_3V3: C30.1 C160.1 C161.1 C242.1 J39.4(VDD) R371.1 U37.A2(VOUT)
VTRG_FAULT_B: R215.2 U31.A2(F\A\U\L\T\) U38.A8(P3_0/I2S0_RX_SCK/I2S0_RX_MCLK/I)
WALL_OV_BASE: Q3.1(B) R5.2
WALL_OV_CTL: D1.C(CATHODE) R3.2 R5.1
WALL_OVP_LED: D2.A Q3.3(C) R10.1
WDOG_B: C60.1 U1.D14(GPIO_B1_13)
N99781517: D4.C D5.C J5.1 R15.1 R16.2
N99781633: C21.1 C22.1 U1.P8(VDD_HIGH_CAP)
N99781636: C25.1 U1.M10(VDD_SNVS_CAP)
N99781637: C24.1 C26.1 U1.P10(NVCC_PLL)
N99781670: L1.2 U1.M1(DCDC_LP_1) U1.M2(DCDC_LP_2)
N99781682: C42.1 U1.N9(RTC_XTALI) Y2.1
N99781687: C43.1 U1.P9(RTC_XTALO) Y2.2
N99781694: C40.1 R28.2 U1.N11(XTALO) Y1.1
N99781701: C39.1 R28.1 R30.1 U1.P11(XTALI) Y1.3
N99781716: C29.1 R18.2 R19.1 U2.3(VCC)
N99781728: R19.2 R20.1 U2.2(R\E\S\E\T\)
N99781740: C60.2 D9.C R45.1
N99781746: D8.A D9.A R41.1 U5.3(M\R\)
N99781747: C47.1 C48.1 J7.2 L2.2 R36.1 TP7.1(TP) U3.5(OUT)
N99781749: C54.1 R35.2 R38.1 R41.2 U3.8(EN) U5.2(R\E\S\E\T\)
N99781753: C58.1 D8.C R43.2
N99781762: C44.1 C45.1 C46.1 R33.2 R35.1 U3.2(VIN)
N99781782: R36.2 R39.1 U3.7(FB)
N99781791: L2.1 U3.3(SW)
N99808656: C77.1 C78.1 R61.2 U1.J6(NVCC_SD0)
N99815013: C140.1 C141.1 L13.2 U16.3(VDDA_3.3)
N99815680: C142.1 C143.1 U16.2(VDD_1.2)
N99815919: C149.1 J19.6(CT1)
N99815924: C150.1 J19.5(CT2)
N99816488: J19.13(SH1) J19.14(SH2) L14.2
N99820323: R133.1 U16.10(REXT)
N99825452: C108.1 C109.1 C110.1 C111.1 R95.2 U13.21(SPKVDD2) U13.26(SPKVDD1)
N99827287: C113.1 U13.27(VMID)
N99827729: R96.2 U13.15(ADCLRC/GPIO1)
N99827749: R98.2 U13.13(DACLRC)
N99827769: R99.2 U13.12(BCLK)
N99827789: R100.2 U13.16(ADCDAT)
N99827809: R101.2 U13.14(DACDAT)
N99827829: R102.2 U13.11(MCLK)
N99827958: C134.2 C232.1 J16.1 R118.2
N99827962: C136.1 C232.2 J16.2 R120.2
N99828318: C135.2 C233.1 J17.1 R119.2
N99828322: C137.1 C233.2 J17.2 R121.2
N99833003: J9.S1(SHLD1) J9.S2(SHLD2) J9.S3(SHLD3) J9.S4(SHLD4) L6.1
N99833017: J9.1(P1) L4.1 U9.6(VBUS)
N99833020: J9.4(P4) R71.1 U9.3(USB ID)
N99833038: J9.2(P2) L5.1 R68.1 U9.1(DM)
N99833040: J9.3(P3) L5.4 R69.1 U9.2(DP)
N99834989: J10.S1(SHLD1) J10.S2(SHLD2) J10.S3(SHLD3) J10.S4(SHLD4) L9.1
N99834993: J10.1(P1) L7.1 U11.6(VBUS)
N99835007: J10.2(P2) L8.1 R83.1 U11.1(DM)
N99835017: J10.3(P3) L8.4 R84.1 U11.2(DP)
N99838171: D12.C R175.1
N99842431: R114.1 R115.2 U14.1(1A)
N99842486: C139.1 R122.2
N99842500: C131.2 T1.1
N99842510: C132.1 R116.1 T1.6
N99842524: C132.2 R115.1
N99842534: R114.2 R117.1 U14.3(2A) U14.6(1Y)
N99842546: J15.2 U14.4(2Y)
N99842626: J38.1 R124.1 U15.2(A)
N99842704: J18.1 T2.3
N99903207: C230.2 L10.1 R97.2
N99903209: C231.2 L11.1 R103.1
N99903219: C115.1 J12.3 L11.2 TVS4.2(A2)
N99903223: C114.2 J12.2 L10.2 TVS2.2(A2)
N99903738: J12.4 L12.2 TVS5.2(A2)
N99904959: C123.2 R107.2 R110.1
N99904961: C125.2 C128.1 C129.1 L12.1 R110.2
N99904975: C119.1 C120.1 R104.2 R107.1
N99907436: C124.2 R112.2 R113.2
N99907447: C126.1 R109.2 R111.2 R112.1
N99907449: C122.1 R106.2 R108.2 R109.1
N99907458: C116.1 C117.1 C124.1 R105.2 R106.1
N99907542: P1.1(OUT) R108.1
N99907546: P1.2(GND) R111.1
N99909350: R268.2 R269.1 U32.7(SA0/MISO)
N99909356: R266.1 U32.16(RST)
N99909379: R273.1 U32.6(SDA/MOSI)
N99909383: R272.1 U32.4(SCL/SCLK)
N99909400: C190.1 U32.2(BYP)
N99909418: C189.1 U32.8(CRST)
N99909466: R264.1 U32.9(INT2)
N99909468: R263.1 U32.11(INT1)
N99909488: R265.2 R267.1 U32.10(SA1/C\S\)
N99912430: C89.1 C90.1 L3.2 R64.2 U8.6(VIN)
N99912683: D10.A(ANODE) L3.1 U8.1(LX)
N99912703: C88.1 D10.C(CATHODE) R63.1 U8.5(OVP)
N99917011: J25.3 J26.2
N99917059: J24.9 R276.1
N99917061: J24.10 R277.1
N99917215: D14.C J25.5
N100002783: C41.1 R32.2 U1.K3(DCDC_PSWITCH)
N100054133: Q4.1(GATE) R10.2 R11.1
N100054172: C1.1 C2.1 C3.1 J1.1(A1) JP1.2 Q2.1(D1) Q2.2(D2) Q2.5(D5) Q2.6(D6) Q2.7(D7) TVS1.2(A2)
N100054253: C5.2 D2.C Q2.3(G) R4.2 R8.1
N100054255: R8.2 R9.1
N100054257: R9.2 SW1.5(COMMON2)
N100054299: C5.1 JP1.1 Q1.4(S1) Q1.8(S2) Q2.4(S1) Q2.8(S2) Q3.2(E) R1.2 R2.2 R3.1 R4.1
N100054525: D3.3(ANODE2) R7.2
N100054552: D3.1(ANODE1) R6.2
N100054568: D3.2(CATHODE1) Q4.3(DRAIN)
N100192090: J35.19 R230.2
N100192374: J35.23 L17.1
N100226351: R246.2 SW7.5(B4)
N100226419: R245.2 SW7.6(B3)
N100226426: R244.2 SW7.7(B2)
N100226433: R243.2 SW7.8(B1)
N100226440: R242.2 SW6.5(B4)
N100226447: R241.2 SW6.6(B3)
N100226454: R240.2 SW6.7(B2)
N100226461: R239.2 SW6.8(B1)
N100226670: R238.2 SW5.5(B4)
N100226677: R237.2 SW5.6(B3)
N100226684: R236.2 SW5.7(B2)
N100226691: R235.2 SW5.8(B1)
N100290781: J8.A31(DISP) R67.2
N100350746: D6.A D7.A R27.2 R29.1
N100395820: C131.1 J14.2
N100395835: J14.1 T1.3
N100531599: C65.1 C66.1 R48.2 U7.3(VIN)
N100538650: Q9.3(DRAIN) R47.2
N100538655: Q9.1(SOURCE) R46.2 R52.1 U6.4(FB)
N100585505: J39.9(DETECT) R173.1 R313.2 R320.1
N100756566: TP22.1(TP) U1.N10(GPANAIO)
N100757315: TP23.1(TP) U1.N12(U\S\B\_\O\T\G\1\_\C\H\D\)
N100763661: J24.5 R278.1
N100763684: J24.4 R279.1
N100763722: J24.6 R280.1
N100763741: J24.3 R281.1
N100763780: R283.2 U20.F2(CLK)
N100784802: J23.1 R285.1
N100784828: J23.2 R286.1
N100784849: J22.4 R287.1
N100784872: J22.1 R288.1
N100784902: J22.2 R289.1
N100784935: J23.3 R290.1
N100784954: J23.4 R291.1
N100873109: R18.1 R293.2
N100881534: R154.2 U33.6(SCK)
N100881537: R153.2 R360.2 U33.1(C\E\)
N100881743: R155.1 U33.5(SI_IO0)
N100881750: R156.1 U33.2(SO_IO1)
N100881757: R157.1 R359.2 U33.3(W\P\_IO2)
N100881764: R158.1 R358.2 U33.7(H\O\L\D\/R\E\S\E\T\_IO3)
N100937722: R168.2 R169.2 U19.A4(R\E\S\E\T\)
N100939369: R171.2 R424.1 R425.1 R427.2
N100979684: R304.1 R305.2 U4.4(FB)
N101050998: C234.1 R322.1 R323.2 U16.32(R\S\T\)
N101100421: R313.1 R371.2 R372.2
N101108824: D18.A(ANODE) R316.2
N101139052: C235.1 C236.1 R328.2 U34.B1(VINT1) U34.B2(VINT2) U34.C1(VINT3)
N101140611: Q15.3(DRAIN) R329.2 R332.2 R333.1 U34.A1(EN)
N101140956: R334.2 R349.2 U34.A2(F\A\U\L\T\)
N101141371: R335.1 U34.A3(ILIM)
N101141743: C237.1 C238.1 R336.2 U35.B1(VINT1) U35.B2(VINT2) U35.C1(VINT3)
N101141921: R341.2 R350.2 U35.A2(F\A\U\L\T\)
N101141946: R342.1 U35.A3(ILIM)
N101142201: R344.2 R346.2 R348.1 U35.A1(EN)
N101241745: C98.1 C99.1 R85.2 U12.3(VCC)
N101242370: C102.1 R88.2 R89.1
N101242461: FL1.4 R87.1 U12.7(CANH)
N101242463: FL1.3 R91.1 U12.6(CANL)
N101242940: R90.2 R92.2 R326.1 U12.8(S)
N101351285: R294.2 R356.2 U19.C2(C\S\1\)
N101351783: C248.1 J35.21 L19.1
N101474013: R361.2 U19.B2(CK)
N101474117: R362.2 U19.D3(DQ0)
N101474142: R363.2 U19.D2(DQ1)
N101474197: R364.2 U19.C4(DQ2)
N101474201: R365.2 U19.D4(DQ3)
N101481296: R366.2 U19.C3(RWDS)
N101508071: R29.2 U37.B1(EN)
N101529304: C254.1 C258.1 C261.1 L24.2 U38.E4(VDDREG1) U38.E5(VDDREG2) U38.F4(VDDREG3)
N101531474: R377.1 R378.2 U40.4(FB)
N101535047: R379.2 U38.E3(USB0_VBUS)
N101535139: R380.2 U38.F3(USB0_RREF)
N101537312: R381.2 U38.A6(DBGEN)
N101537315: R382.2 U38.B6(R\E\S\E\T\)
N101537383: R383.2 U38.A4(WAKEUP0)
N101544777: R387.2 U38.C9(P6_11/GPIO3[7]/EMC_CKEOUT0/T2_M)
N101546218: D20.A(ANODE) R392.2
N101549401: J43.1 R394.2 R400.2 U44.2(A1)
N101549759: R402.1 U44.5(OE)
N101553401: R413.2 U45.6(OE)
N101556572: R416.1 U48.7(1B)
N101556596: R417.1 U48.6(2B)
N101557543: R418.1 U48.5(DIR)
N101571275: C273.1 U38.C1(XTAL2) Y4.2
N101571285: C274.1 U38.B1(XTAL1) Y4.1
N101599117: R351.1 U31.A3(ILIM)
N101599129: R212.2 R214.1 R216.2 U31.A1(EN)
N101616215: R424.2 U19.A3(RFU1)
N101616337: R425.2 U19.A2(R\S\T\O\)
N101616340: R426.2 U19.A5(I\N\T\)
N101658009: R170.2 R426.1

Pads without a net: J1 7; J8 A35 A37 A38 A39 A40; J10 4; J12 6; J19 9; J25 1; J34 7 9; J35 24; SW1 1 2 4; U1 N13 P13; U9 4 5; U11 3 4 5; U13 3 30; U16 8 22 26 27; U17 5; U19 B5 C5; U20 E2; U32 15; U38 A1 A2 A3 A5 A7 A9 A10 B3 B5 B7 B8 B9 C3 C7 D6 D7 D8 D9 E6 E7 E8 E9 E10 F5 F6 F8 F9 G1 G2 G4 G5 G6 G9 H1 H4 H5 H6 H7 H8 H9 J1 J2 J5 J7 J9 K3 K6 K7 K8 K9 K10

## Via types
v1: diameter 0.356, hole 0.203, TOP to BOTTOM, 130 vias
v2: diameter 0.457, hole 0.203, TOP to BOTTOM, 1544 vias

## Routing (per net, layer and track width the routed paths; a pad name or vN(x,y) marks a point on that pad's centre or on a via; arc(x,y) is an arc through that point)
5V_SDA_PSW: length 0.8
  TOP w0.254: U31.D1 U31.D2 U31.C2
5V_SYS: length 21
  TOP w0.381: J25.8 29.9,30.79 28.19,29.08 v2(27.05,29.08) D14.A ; R7.1 v2(20.95,22.73)
  BOTTOM w0.381: R85.1 76.58,20.45 77.34,19.68 77.34,15.5 v2(75.69,13.84) ; v2(20.95,22.73) 22.1,23.88 25.53,23.88
  vias: v2(28.85,21.87) v2(29.44,22.23) v2(29.44,21.59) v2(30.1,22.23) v2(33.02,39.37) v2(35.18,39.98) v2(36.07,39.98) v2(53.47,14.22) v2(53.47,13.46) v2(53.47,12.7) v2(82.68,9.53) v2(83.57,9.53) v2(86.49,18.92) v2(87.25,18.92) v2(91.31,58.17) v2(92.2,58.17) v2(93.09,58.17) v2(93.85,58.17) v2(97.28,18.54) v2(97.28,17.78) v2(97.28,17.02) v2(97.54,28.07) v2(97.54,27.05) v2(98.17,27.43) v2(98.17,26.54) v2(98.17,18.54) v2(98.17,17.78) v2(98.17,17.02)
5V_USB_HS: length 56.7
  TOP w0.254: C84.1 57.02,45.84 56.74,46.12 56.74,46.71 v2(57.28,47.24) 57.28,50.04 57.44,50.21 U1.P6
  TOP w0.381: L7.2 C97.1 78.11,9.5 78.49,9.89 78.49,13.34 79.12,13.97 v2(79.12,20.19)
  BOTTOM w0.305: 59.44,43.05 58.39,44.09 58.39,45.66 58.04,46.02 58.04,46.71 57.51,47.24 v2(57.28,47.24)
  BOTTOM w0.381: 59.44,43.05 62.09,40.4 62.09,31.25 68.71,24.64 75.95,24.64 76.96,23.62 78.99,23.62
  vias: v2(88.14,20.19) v2(88.52,20.83) v2(88.9,20.19)
5V_USB_OTG: length 50.8
  TOP w0.127: 57.77,50.04 57.77,51.34 U1.N6
  TOP w0.254: 57.77,50.04 57.83,49.98 57.83,47.03 v2(57.28,46.48)
  TOP w0.305: v2(78.11,14.1) v2(78.11,18.8)
  BOTTOM w0.305: v2(57.28,46.48) C79.1 57.53,45.84 57.91,45.46 57.91,43.81 58.78,42.95
  BOTTOM w0.381: 58.78,42.95 58.78,42.57 61.53,39.81 61.53,30.42 68.2,23.75 75.18,23.75 78.11,20.83 v2(78.11,18.8)
  vias: v2(87.12,10.79) v2(87.12,9.91) v2(87.12,9.02)
GND: length 624.2
  TOP w0.127: v2(128.41,70.97) 126.85,70.97
  TOP w0.203: v2(142.49,90.42) 142.86,90.06 U44.4 ; U1.P14 62.9,51.02 v1(63.25,50.67) ; U1.N1 U1.N2
  TOP w0.254: v2(48.51,53.34) 48.26,53.34 v2(47.62,52.7) v2(46.86,51.94) v2(46.1,51.18) v2(45.34,50.42) 42.67,47.75 C34.2 C33.2 40.63,47.75 v2(40.51,47.62) v2(38.73,47.62) v2(37.97,47.62) v2(36.45,47.62) v2(35.69,47.62) v2(34.29,47.62) v2(31.62,47.62) 31.37,47.62 v2(28.57,50.42) v2(28.57,53.09) v2(28.57,55.63) v2(28.57,58.17) v2(28.57,62.87) v2(29.84,64.14) v2(31.11,65.41) 32.13,66.42 v2(39.24,66.42) v2(41.15,66.42) v2(43.05,66.42) v2(44.96,66.42) v2(46.86,66.42) v2(48.51,66.42) v2(50.42,66.42) v2(52.32,66.42) 53.09,66.42 v2(53.98,65.53) v2(55.12,64.39) v2(56.26,63.25) v2(57.15,62.36) ; U1.G7 v1(57.77,55.89) ; v2(57.35,44.45) 57.38,44.48 C84.2 ; C56.2 v2(32.64,19.81) ; R251.1 v2(82.68,65.91) ; C55.2 v2(32.64,20.95) ; U1.K13 v1(61.67,53.95) ; C220.2 89.15,65.66 v2(88.52,66.29) R254.1 ; U1.N5 v1(56.47,51.35) ; C198.2 83.69,50.29 v2(84.07,50.67) ; U1.A1 v1(53.87,59.79) ; v2(128.65,69.72) 128.27,69.34 v2(122.17,69.34) ; U13.24 129.39,22.89 128.91,23.37 v2(128.91,23.62) ; v2(56.64,77.6) 56.77,77.47 U32.3 ; U32.5 56.79,76.47 v2(56.64,76.33) ; R125.2 v2(124.09,45.85) ; U1.K2 v1(54.52,53.3) ; v2(127.64,23.62) 127.38,23.37 U13.20 ; U20.E3 v2(34.06,59.78) ; U20.A3 v2(37.25,59.78) ; U13.28 129.14,24.65 v2(128.91,24.89) ; v2(97.41,90.93) 97.03,90.93 96.76,91.2 U48.4 ; v1(55.22,40.56) 55.02,40.76 U19.B3 ; U14.2 v2(124.97,57.29) ; R31.2 v2(91.01,76.91) ; v2(84.96,68.34) 85.08,68.45 R253.1 ; C43.2 62.48,47.12 v2(62.1,46.74) 61.65,46.29 61.65,44.26 62.09,43.83 v2(63.25,43.83) v2(64.81,43.83) 65.68,43.83 66.04,44.19 66.04,46.48 v2(65.79,46.74) 65.41,47.12 C42.2 ; C199.2 89.15,46.23 89.31,46.08 89.31,45.24 v2(89.03,44.96) ; U1.L9 v1(59.72,53.3) U1.K9 ; v2(65.02,78.11) 64.89,77.97 U32.12 ; v2(106.3,42.07) 106.95,42.72 U16.1 ; 126.85,70.97 126.49,70.61 v2(125.35,70.61) 123.06,70.61 v2(122.81,70.87) ; R248.1 R249.1 v2(79.55,68.45) ; U1.G8 v1(59.07,55.89) ; v2(67.56,43.56) 67.43,43.69 C26.2 C24.2 67.43,45.73 67.18,45.97 67.18,47.12 65.79,48.51 64.64,48.51 64.52,48.64 v2(64.14,48.64) 64.03,48.74 62.71,48.74 v2(61.98,49.48) ; v1(132.46,67.18) 131.92,66.64 U31.D3 ; U31.C3 131.52,66.87 v1(131.83,67.18) ; U1.E2 v1(54.52,56.54) ; U1.B5 v1(56.47,59.14) ; U20.D7 v2(34.86,55.79) ; v2(57.02,37.21) 57.02,37.48 U19.E5 ; R257.1 v2(83.81,67.74) ; v1(53.79,51.24) 53.79,51.26 U1.N1 ; U1.A14 v1(62.97,59.79) ; U20.C3 v2(35.65,59.78) ; U20.J1 v2(30.06,61.38) ; v1(53.47,50.8) 53.98,50.8 U1.P1 ; R250.1 v2(82.03,67.77) ; U31.B3 131.12,67.11 v1(131.19,67.18) ; R414.2 v2(111.63,91.69) ; U1.J7 v1(57.77,53.95) U1.K6 ; R256.1 86.1,66.92 v2(86.23,67.06) ; U1.H8 v1(58.42,54.6) U1.J8 ; R303.2 v2(70.48,56.9) ; R267.2 68.07,76.58 v2(68.33,76.33) ; U1.E13 v1(62.32,57.19) ; U1.H7 v1(57.77,54.6) ; R185.2 38.1,61.34 38.06,61.38 v2(37.25,61.38) U20.A1 ; v2(124.33,26.66) U13.9 ; U1.N8 v1(58.42,51.99) ; U32.13 64.37,78.47 64.64,78.74 v2(65.02,78.74) ; v2(37.34,18.41) R39.2 ; U37.B2 v1(27.49,38.81) ; R252.1 v2(88.63,68.31) ; U1.B10 v1(60.37,59.14) ; U20.B7 v2(36.46,56.59)
  TOP w0.305: U38.D5 v2(129.21,73.37) ; v2(128.41,71.77) U38.C2 v2(128.41,70.97) ; v2(59.82,44.96) 59.81,44.96 C21.2 ; U38.F2 v2(131.61,70.97) ; U38.J6 v2(134.01,74.97) ; U46.2 v2(112.52,97.41) ; U38.D3 v2(129.21,71.77) ; v2(127.76,6.35) 127.47,6.65 J35.2 ; U38.D4 v2(129.21,72.57) ; C58.2 v2(40.13,16.38) ; v2(126.96,6.35) J35.1 ; v1(52.2,40.16) 52.59,39.76 U19.C1 ; C258.2 v2(125.48,67.49) ; R333.2 v2(84.71,16.76) ; C275.2 v2(115.57,91.31) ; J35.10 v2(131.47,6.35) ; C4.2 v2(16.64,11.56) ; U38.G8 v2(131.61,76.57) ; U38.J3 v2(134.01,71.77) ; v2(114.43,91.95) 114.17,91.69 C276.2 ; U38.C8 v2(128.41,76.57)
  TOP w0.381: C27.2 62.48,41.53 v2(62.38,41.43) ; v2(51.82,73.37) SW8.2 ; C148.2 v2(114.94,31.13) ; TVS5.1 v2(146.43,25.32) ; v2(83.95,23.24) C237.2 v2(84.96,24.38) ; v2(67.56,48.88) C40.2 68.38,48.88 68.92,49.43 71.98,49.43 72.39,49.02 v2(72.39,48.26) ; C165.2 38.1,60.33 37.56,59.78 v2(37.25,59.78) ; C128.2 v2(130.56,33.27) ; D3.4 v2(20.11,16) ; C234.2 105.76,41.53 v2(106.3,42.07) ; R150.2 v2(112.9,52.96) ; Q15.1 81.27,18.53 v2(81.66,18.92) ; R259.1 v2(90.67,81.03) ; U49.5 94.61,86.36 v2(94.49,86.23) C278.2 ; C185.2 v2(133.6,64.77) ; R214.2 v2(128.4,63.75) ; R152.2 R146.2 v2(107.19,52.99) ; v2(96.77,66.17) 97.28,66.68 U8.2 v2(98.93,66.68) ; 60.33,65.66 59.56,65.66 v2(59.44,65.53) C70.2 C69.2 v2(59.44,64.39) ; U40.2 v2(144.15,78.74) ; SW9.2 v2(140.17,97.5) ; TVS2.1 136.99,24.3 v2(136.78,24.51) ; v2(44.07,38.1) R54.2 ; R377.2 v2(146.43,84.2) ; v2(58.67,13.08) 58.55,13.21 C52.2 ; C257.2 v2(140.84,76.96) ; C169.2 40.01,54.86 v2(39.62,55.24) 40.01,55.63 C167.2 ; v2(119.89,30.99) 120.14,31.24 C117.2 ; C121.1 v2(128.78,30.86) ; R149.2 v2(102.49,43.47) ; R258.1 92.65,69.4 v2(92.65,69.23) 92.34,68.91 R314.2 ; v2(69.6,44.83) 68.96,44.83 68.71,45.09 C39.2 ; v2(69.6,44.83) v2(70.99,44.83) 72.01,44.83 72.22,45.04 R30.2 72.9,45.04 73.33,45.48 73.33,46.43 72.9,46.86 v2(72.66,46.86) 72.39,47.13 v2(72.39,48.26) ; v2(69.6,44.83) 69.74,44.97 Y1.2 ; U2.1 v2(64.81,43.83) ; U12.2 75.32,21.32 v2(75.44,21.21) ; C103.2 v2(69.34,9.4) ; C23.2 v2(77.47,36.96) ; v2(140.46,11.94) 140.46,11.68 L17.2 ; C134.1 v2(146.3,22.23) ; C120.2 v2(129.79,35.19) ; R11.2 v2(16.26,14.99) ; v2(139.06,71.88) R389.2 R380.1 ; v2(138.81,74.8) 139.33,74.8 D20.C ; C54.2 38.23,20.87 v2(38.3,20.95) ; C68.2 v2(45.72,17.78) ; R117.2 120.57,56.34 v2(120.52,56.39) ; SW2.1 v2(58.97,2.83) ; v2(142.24,83.57) C255.2 v2(139.95,83.57) ; v2(9.13,44.69) C242.2 v2(9.13,42.43) ; C137.2 v2(137.16,22.23) ; v2(63.5,9.4) C101.1 ; C260.2 v2(141.1,79.12) ; v2(122.94,80.26) R391.2 R387.1 ; v2(136.02,25.78) R103.2 R97.1 ; v2(63.25,81.53) C187.2 ; U33.4 v2(60.07,28.45) ; C48.2 v2(38.61,10.03) ; TVS4.1 v2(136.2,38.61) ; C118.1 v2(125.22,30.86) ; C273.2 122.05,69.22 v2(122.17,69.34) ; C127.2 v2(130.56,30.86) ; v2(75.31,14.99) 75.81,14.48 R326.2 ; 8.31,46.13 v2(8.31,44.76) ; 114.43,83.95 v2(114.43,83.06) ; C62.2 31.88,39.24 v2(31.96,39.16) ; C7.2 C6.2 v2(70.99,50.04) ; U45.2 v2(117.29,96.08) ; C71.2 v2(55.37,65.53) ; v2(31.37,45.47) C223.2 32.13,46.48 31.62,46.99 v2(31.62,47.62) ; C203.2 126.9,12.73 v2(126.9,12.06) ; SW9.1 v2(126.66,97.5) ; C252.2 v2(29.58,35.69) ; C53.2 v2(58.67,12.06) ; C57.2 v2(82.04,42.67) ; C119.2 v2(128.78,34.92) ; C115.2 133.86,23.75 v2(133.45,24.15) C113.2 ; v2(50.55,47.75) v2(50.55,45.85) v2(50.55,45.21) ; R260.1 v2(88.27,80.26) ; Q4.2 v2(19.35,14.1) ; C146.2 v2(108.08,38.39) ; C208.2 v2(102.87,76.07) ; C186.2 v2(113.41,84.84) ; v2(82.3,14.61) C235.2 v2(81.28,13.46) ; R140.2 v2(102.49,46.64) ; C268.2 v2(145.29,85.6) ; C114.1 v2(133.73,28.96) ; C212.2 83.19,55.37 v2(83.31,55.24) ; C277.2 v2(93.6,97.41) ; C149.2 v2(109.73,31.91) ; C200.2 v2(91.57,21.46) ; R351.2 v2(127.64,68.33) ; C259.2 v2(141.35,78.23) ; SW3.1 v2(44.7,2.83) ; v2(72.39,48.26) Y1.4 ; C49.2 v2(58.55,16) ; R304.2 v2(58.67,9.53) ; v2(39.62,42.9) 39.88,43.15 C31.2 ; v2(89.41,11.94) 88.99,11.52 C93.2 ; v2(39.5,17.14) 39.5,17.15 R45.2 ; C190.2 v2(54.23,78.23) ; C129.2 v2(131.57,33.27) ; C189.2 v2(63.5,69.97) ; J19.10 v2(105.65,28.86) ; C238.2 v2(84.33,22.1) ; v2(139.45,22.23) C135.1 ; R135.2 v2(114.8,49.05) ; R141.2 v2(111.76,52.96) ; C29.2 v2(65.98,37.59) ; R137.2 v2(114.94,46.9) ; R133.2 v2(114.94,42.58) ; C207.2 v2(40.89,85.47) ; R255.1 85.35,69.47 85.1,69.22 v2(84.45,69.22) 84.44,69.2 84.44,68.95 R247.1 ; C112.2 v2(131.57,30.86) ; C138.2 v2(118.12,52.1) ; U17.2 v2(107.06,35.08) ; C272.2 v2(127.89,90.81) ; R52.2 v2(39.62,35.05) ; U39.1 v2(141.1,71.5) ; R181.2 v2(32.02,85.85) ; R180.2 v2(34.56,85.85) ; C241.2 v2(135.13,66.93) ; 9.24,59.28 v2(9.24,60.8) ; C15.2 v2(68.45,50.04) ; C209.2 v2(33.27,85.47) ; U49.2 v2(94.61,90.42) ; C144.2 v2(113.67,38.26) ; C240.2 v2(84.59,10.79) ; R113.1 v2(123.7,32.01) ; C47.2 v2(40.01,10.03) ; C229.2 v2(55.88,17.14) ; J39.6 v2(13.46,56.28) ; C188.2 v2(54.23,79.25) ; C59.2 v2(41.91,24.81) ; C147.2 v2(104.78,38.39) ; C67.2 v2(45.72,18.92) ; C97.2 v2(77.72,11.02) ; SW2.2 v2(45.72,2.83) ; v2(133.48,13.34) 133.35,13.46 C204.2 ; C136.2 v2(144.02,22.23) ; C145.2 v2(110.36,38.26) ; C270.2 v2(146.56,87.38) ; SW8.1 v2(38.39,73.37) ; TVS3.1 v2(142.69,24.95) ; C236.2 v2(81.66,12.32) ; SW3.2 v2(31.66,2.83) ; C150.2 v2(110.75,31.91) ; R266.2 v2(59.05,81.53) ; R269.2 v2(62.23,69.98) ; C116.2 v2(121.03,31.37) ; U15.3 v2(120.27,50.78) ; 121.28,72.26 v2(120.4,72.26) ; R335.2 v2(88.77,17.02) ; U5.1 v2(38.78,24.64) ; D11.3 v2(68.25,3.99) ; v2(145.03,74.93) 145.03,74.57 145.41,74.19 J41.5 ; C216.2 v2(78.61,77.09) ; R148.2 v2(102.49,44.48) ; C196.2 v2(119.76,25.4) ; R348.2 v2(88.39,27.18) ; 121.28,57.29 v2(120.52,57.29) ; C30.2 v2(27.06,35.69) ; R182.2 v2(21.86,85.85) ; C130.2 v2(127,30.86) ; C22.2 C21.2 ; D1.A v2(13.84,20.96) ; Q1.3 v2(14.99,15.89) ; R342.2 v2(91.44,27.43)
  GND w0.102: 57.45,56.87 57.45,56.1 ; 57.45,56.87 57.45,57.52 ; 57.45,56.87 56.8,56.87 ; 57.45,56.87 61.58,56.87 ; 57.45,57.52 57.45,58.17 ; 57.45,57.52 56.8,57.52 ; 57.45,57.52 61.58,57.52 ; 56.15,56.87 56.8,56.87 ; 56.15,56.87 55.5,56.87 ; 56.15,56.87 56.15,57.52 ; 56.15,56.87 56.15,56.22 ; 56.8,56.87 56.8,51.59 ; 56.8,56.87 56.8,57.52 ; 55.5,56.87 55.5,56.22 ; 55.5,56.87 54.76,56.87 ; 55.5,56.87 55.5,57.52 ; 55.5,56.22 54.76,56.22 ; 55.5,56.22 55.5,52.07 55.5,52.07 ; 55.5,56.22 56.15,56.22 ; 58.85,53.62 62,53.62 ; 54.89,52.32 62.1,52.32 ; 61.35,51.44 61.35,53.76 ; 56.8,58.67 56.8,58.17 ; 56.8,58.17 56.15,58.17 ; 56.8,58.17 57.45,58.17 ; 56.8,58.17 56.8,57.52 ; 58.09,51.66 58.09,53.55 ; 56.15,56.22 56.15,51.83 56.13,51.82 ; 56.15,56.22 57.53,56.22 ; 58.29,58.17 57.45,58.17 ; 58.29,58.17 58.29,58.17 ; 58.29,58.17 61.58,58.17 ; 57.45,58.17 57.45,58.67 ; 56.15,57.52 56.15,58.17 ; 56.15,57.52 56.8,57.52 ; 56.15,57.52 55.5,57.52 ; 56.15,58.17 56.15,58.92 ; 56.15,58.17 55.5,58.17 ; 54.85,54.27 57.32,54.27 ; 55.5,57.52 55.5,58.17 ; 55.5,57.52 54.76,57.52 ; 55.5,58.67 55.5,58.17 ; 55.5,58.17 54.76,58.17 ; 60.05,54.25 60.05,58.89 ; 61.35,54.12 61.35,58.89 ; 59.91,52.97 62.09,52.97 ; 59.31,56.22 61.58,56.22 ; 54.85,53.62 57.32,53.62 ; 59.4,56.1 59.4,58.89 ; 57.45,51.98 57.45,53.55 ; 54.85,52.97 59.28,52.97 ; 59.95,51.67 62.1,51.67 ; 60.7,50.94 60.7,58.89 ; 58.44,54.27 62.19,54.27 ; 59.4,54.14 59.4,55.46
  INT1 w0.102: 55.5,56.21 55.5,55.67 ; 55.5,56.21 55.48,56.22 ; 55.5,56.21 55.5,57.51 ; 56.22,56.22 55.48,56.22 ; 55.48,56.22 54.94,56.22 ; 56.8,57.52 56.8,58.19 ; 56.8,57.52 56.8,56.92 ; 56.8,57.52 55.5,57.52 55.5,57.51 ; 56.8,58.19 56.8,58.92 ; 56.8,58.19 56.78,58.17 55.5,58.17 55.5,58.17 ; 56.15,58.67 56.15,56.87 54.76,56.87 ; 55.5,59.18 55.5,57.51
  BOTTOM w0.102: C77.2 57.28,53.27 57.77,53.76 v1(57.77,53.95) ; v1(56.47,59.14) U1.B5 56.79,56.94 C13.2
  BOTTOM w0.254: C100.2 v2(75.31,16) ; J8.A5 v2(92.65,69.23) ; v1(54.52,53.3) 54.48,53.33 C35.2 ; v2(31.62,47.62) v2(29.21,47.62) v2(24.51,47.62) v2(21.97,47.62) ; C16.2 v2(68.45,50.04) ; C170.2 34.8,55.84 v2(34.86,55.79) ; J8.A3 v2(93.65,69.23) ; C245.2 37.2,47.62 v2(36.45,47.62) v2(35.69,47.62) v2(34.29,47.62) ; J8.A13 v2(88.65,71.82) ; J8.A6 v2(92.15,71.82) ; J8.A21 v2(84.65,71.82) ; v2(28.57,58.17) v2(28.57,55.63) v2(28.57,53.09) v2(28.57,50.42) 29.06,49.94 v2(35.2,49.94) v2(35.92,49.94) v2(37.59,49.94) 41.27,49.94 v2(41.4,50.06) v2(42.06,50.06) 44.98,50.06 v2(45.34,50.42) v2(46.1,51.18) v2(46.86,51.94) v2(47.62,52.7) 48.26,53.34 v2(48.51,53.34) ; R173.2 24.13,53.98 ; C248.2 v2(136.65,5.97) ; v2(36.46,56.59) 36.2,56.85 C168.2 ; J8.B6 33.01,71.13 32.64,71.5 v2(32.64,71.63) ; R172.2 v2(19.94,52.7) ; J8.A22 84.15,69.52 v2(84.45,69.22) ; v2(35.65,59.78) 35.56,59.69 C166.2 ; C244.2 40.51,47.63 v2(40.51,47.62) ; J8.A29 v2(80.65,71.82) ; C82.2 63.98,48.49 v2(64.14,48.64) ; C72.2 59.34,55.89 v1(59.07,55.89) ; J8.A36 v2(77.15,69.23) ; J8.A23 v2(83.65,71.82) ; C102.2 v2(66.42,9.78) ; J8.A14 v2(88.15,69.23) ; J8.A7 v2(91.65,69.23) ; v2(37.97,47.62) v2(38.73,47.62) ; C19.2 59.81,53.39 v1(59.72,53.3) 59.77,53.25 C25.2
  BOTTOM w0.305: C163.2 v1(57.4,40.89) ; v2(131.61,70.97) 131.95,71.31 C261.2 ; v2(128.65,69.72) 128.4,69.47 127.76,69.47 ; v2(131.61,76.57) 131.37,76.33 C264.2 ; 60.83,50.29 61.16,50.29 v2(61.98,49.48) ; C263.2 134.1,75.06 v2(134.01,74.97) ; v2(129.21,71.77) 129.32,71.88 C265.2 ; v2(78.61,65.02) 78.99,64.64 C221.2 ; 129.16,75.18 C254.2 129.16,73.42 v2(129.21,73.37) ; v1(53.79,51.24) 53.82,51.27 C41.2 ; v2(128.41,71.77) 128.4,71.78 C262.2
  BOTTOM w0.33: C78.2 52.7,49.78 53.09,50.16 v1(53.09,50.42)
  BOTTOM w0.381: C99.2 73.16,21.6 v2(72.77,21.21) ; v2(68.93,81.41) 68.93,80.8 C214.2 ; v2(102.49,44.48) 102.62,44.61 R143.2 ; C140.2 v2(109.98,44.23) ; C141.2 108.97,43.97 v2(108.71,44.23) ; v2(109.98,45.5) 110.65,44.83 C193.2 ; C219.2 v2(86.23,60.2) ; C161.2 v2(8.51,51.05) ; v2(77.85,26.16) 77.47,25.78 77.09,25.78 v2(77.09,24.89) ; v2(88.9,53.92) 89.36,53.47 C197.2 ; v2(38.73,47.62) 38.74,47.63 C244.2 ; v2(102.74,58.67) 102.11,59.31 C217.2 ; C92.2 36.07,74.68 v2(36.32,74.93) ; R136.2 114.55,48.8 v2(114.8,49.05) ; v2(57.35,44.45) 57.28,44.53 C79.2 ; C195.2 v2(118.36,22.48) ; v2(37.97,47.62) 37.97,47.63 C245.2 ; C194.2 120.4,22.68 v2(120.7,22.99) ; v1(53.09,50.42) 52.83,50.67 C32.2 ; v2(75.44,21.21) 75.82,21.59 C98.2 ; 130.94,11.18 130.94,12.01 v2(130.91,12.04) ; C205.2 135.64,13.34 v2(135.25,12.95) ; C246.2 v2(131.44,8.89) ; C249.2 135.38,10.03 v2(135,9.65) ; C81.2 55.58,49.16 C80.2 54.99,48.64 v2(55.12,48.51) ; v2(57.02,37.21) 57.02,36.83 57.24,36.62 C162.2 ; C218.2 v2(66.17,66.55) ; L14.1 v2(109.22,13.88) ; v2(106.3,42.07) 106.17,41.94 C143.2 ; C215.2 86.07,82.9 v2(86.07,81.79) ; C247.2 131.85,6.73 v2(131.47,6.35) ; C142.2 107.82,43.85 v2(107.44,44.23) ; C222.2 v2(10.54,56.39) ; C164.2 v2(32.26,58.25) ; v2(126.36,26.16) 126.24,26.29 C106.2 ; C107.2 129.29,26.54 v2(128.91,26.16) ; v2(110.11,50.06) 109.73,50.44 C210.2 ; C160.2 v2(8.64,54.1) ; C211.2 v2(105.99,48.9) ; 76.07,83.95 v2(76.07,84.84) ; C171.2 v1(30.06,56.81)
  vias: v1(57,40.26) v2(0.89,99.11) v2(0.89,93.4) v2(0.89,91.49) v2(0.89,89.59) v2(0.89,87.68) v2(0.89,85.78) v2(0.89,83.87) v2(0.89,81.97) v2(0.89,80.06) v2(0.89,78.16) v2(0.89,76.25) v2(0.89,74.35) v2(0.89,72.44) v2(0.89,70.54) v2(0.89,68.63) v2(0.89,66.73) v2(0.89,64.82) v2(0.89,62.92) v2(0.89,61.01) v2(0.89,59.11) v2(0.89,57.2) v2(0.89,55.3) v2(0.89,53.39) v2(0.89,51.49) v2(0.89,49.58) v2(0.89,47.68) v2(0.89,45.77) v2(0.89,43.87) v2(0.89,41.96) v2(0.89,40.06) v2(0.89,38.15) v2(0.89,36.25) v2(0.89,34.34) v2(0.89,32.44) v2(0.89,30.53) v2(0.89,28.63) v2(0.89,26.72) v2(0.89,24.82) v2(0.89,22.91) v2(0.89,21.01) v2(0.89,11.48) v2(0.89,9.58) v2(0.89,7.67) v2(0.89,5.77) v2(0.89,3.86) v2(0.89,1.96) v2(1.91,44.83) v2(2.29,59.94) v2(2.29,58.93) v2(2.29,57.33) v2(2.29,55.42) v2(2.29,53.52) v2(2.29,51.61) v2(2.29,49.71) v2(2.29,47.8) v2(2.29,45.9) v2(2.54,89.53) v2(2.54,86.36) v2(2.54,77.47) v2(2.54,75.56) v2(2.54,73.66) v2(2.54,71.75) v2(2.54,69.85) v2(2.54,67.94) v2(2.54,66.04) v2(2.54,64.14) v2(2.54,62.23) v2(2.54,43.81) v2(2.54,41.91) v2(2.54,40.01) v2(2.54,38.1) v2(2.54,36.2) v2(2.54,34.29) v2(2.54,32.38) v2(2.54,30.48) v2(2.54,28.57) v2(2.54,22.86) v2(2.47,0.89) v2(3.81,91.44) v2(3.81,88.27) v2(4.37,0.89) v2(5.08,90.17) v2(5.08,29.21) v2(5.08,27.3) v2(5.08,25.4) v2(5.71,76.2) v2(5.71,74.3) v2(5.71,72.39) v2(5.71,70.48) v2(5.71,68.58) v2(5.71,66.67) v2(5.71,64.77) v2(5.71,62.87) v2(5.71,40.26) v2(5.71,38.73) v2(5.71,36.83) v2(5.71,34.92) v2(5.71,33.02) v2(5.71,24.13) v2(5.71,22.86) v2(5.97,55.24) v2(5.97,53.34) v2(5.97,51.44) v2(5.97,49.53) v2(5.97,47.62) v2(5.97,45.72) v2(5.97,43.81) v2(5.97,41.91) v2(6.35,92.08) v2(6.35,27.94) v2(6.28,0.89) v2(6.36,99.11) v2(6.73,42.29) v2(6.99,90.17) v2(7.11,62.1) v2(7.11,60.2) v2(7.11,58.29) v2(7.11,56.39) v2(7.11,54.48) v2(7.11,52.58) v2(7.11,50.67) v2(7.11,48.77) v2(7.62,97.79) v2(7.62,93.98) v2(7.62,37.47) v2(7.62,35.56) v2(7.62,33.66) v2(7.62,31.75) v2(7.62,29.84) v2(7.62,26.04) v2(8.26,99.11) v2(8.89,76.2) v2(8.89,74.3) v2(8.89,72.39) v2(8.89,70.48) v2(8.89,68.58) v2(8.89,66.67) v2(8.89,64.77) v2(8.89,62.87) v2(9.14,48.39) v2(9.27,57.4) v2(9.53,97.16) v2(9.53,95.25) v2(9.53,93.34) v2(10.17,99.11) v2(11.43,97.79) v2(11.43,95.89) v2(11.68,49.28) v2(12.07,99.11) v2(12.06,76.2) v2(12.06,74.3) v2(12.06,72.39) v2(12.06,70.48) v2(12.06,68.58) v2(12.06,66.67) v2(12.06,64.77) v2(12.06,62.87) v2(12.7,96.52) v2(12.83,46.48) v2(13.21,24.38) v2(13.21,23.37) v2(13.84,76.07) v2(13.84,74.17) v2(13.84,72.26) v2(13.84,70.36) v2(13.84,68.45) v2(13.84,66.55) v2(13.84,65.66) v2(13.84,64.01) v2(13.84,62.74) v2(13.84,22.23) v2(13.9,0.89) v2(13.98,99.11) v2(14.1,52.96) v2(14.22,60.96) v2(14.35,49.53) v2(14.35,40.13) v2(14.61,78.11) v2(14.86,77.22) v2(14.86,75.31) v2(14.86,73.41) v2(14.86,71.5) v2(14.86,69.6) v2(14.86,67.69) v2(15.11,61.98) v2(15.11,57.66) v2(15.24,43.43) v2(15.8,0.89) v2(15.88,99.11) v2(15.88,47.75) v2(16.26,60.96) v2(16.51,78.11) v2(16.51,76.07) v2(16.51,74.17) v2(16.51,72.26) v2(16.51,70.36) v2(16.51,68.45) v2(16.51,66.55) v2(16.51,64.64) v2(16.51,62.74) v2(16.89,49.28) v2(16.97,57.28) v2(17.27,58.17) v2(17.4,37.34) v2(17.53,77.22) v2(17.53,75.31) v2(17.53,73.41) v2(17.53,71.5) v2(17.53,69.6) v2(17.53,67.69) v2(17.53,46.1) v2(17.65,53.47) v2(17.71,0.89) v2(17.79,99.11) v2(18.03,61.21) v2(18.67,59.82) v2(18.67,57.28) v2(18.67,54.86) v2(18.67,47.62) v2(18.92,66.55) v2(18.92,64.64) v2(18.92,62.74) v2(19.05,43.43) v2(19.18,35.81) v2(19.43,77.98) v2(19.43,76.07) v2(19.43,74.17) v2(19.43,72.26) v2(19.43,70.36) v2(19.43,68.45) v2(19.61,0.89) v2(19.69,99.11) v2(19.81,58.8) v2(19.81,56.9) v2(20.57,40.77) v2(20.95,53.72) v2(20.95,50.29) v2(21.34,61.47) v2(21.52,0.89) v2(21.6,99.11) v2(21.59,46.1) v2(22.1,68.07) v2(22.1,64.52) v2(23.11,62.1) v2(23.42,0.89) v2(23.5,99.11) v2(23.62,76.83) v2(23.75,73.79) v2(23.88,53.47) v2(24.13,68.07) v2(24.13,64.52) v2(24.51,46.1) v2(25.33,0.89) v2(25.41,99.11) v2(25.53,76.83) v2(25.53,73.79) v2(27.23,0.89) v2(27.31,99.11) v2(28.83,20.57) v2(28.83,19.43) v2(28.83,18.03) v2(28.83,16.76) v2(29.14,0.89) v2(29.22,99.11) v2(29.97,58.67) v2(29.97,46.23) v2(31.04,0.89) v2(31.12,99.11) v2(32.95,0.89) v2(33.03,99.11) v2(33.53,75.56) v2(33.78,36.83) v2(34.16,16.06) v2(34.67,16.71) v2(34.67,15.62) v2(34.8,72.9) v2(34.93,99.11) v2(34.85,0.89) v2(35.05,37.97) v2(35.56,88.01) v2(36.07,20.95) v2(36.55,41.88) v2(36.84,99.11) v2(36.76,0.89) v2(37.21,37.97) v2(37.34,39.5) v2(38.48,88.01) v2(38.74,99.11) v2(38.66,0.89) v2(40.65,99.11) v2(40.57,0.89) v2(42.47,0.89) v2(42.55,99.11) v2(43.18,77.47) v2(43.31,88.01) v2(43.81,26.67) v2(43.81,25.4) v2(43.94,45.59) v2(44.38,0.89) v2(44.46,99.11) v2(45.97,39.24) v2(46.23,23.24) v2(46.23,21.08) v2(46.28,0.89) v2(46.36,99.11) v2(47.12,39.24) v2(48.19,0.89) v2(48.27,99.11) v2(48.26,39.24) v2(48.9,41.27) v2(48.9,40.13) v2(49.53,26.67) v2(49.53,25.4) v2(50.09,0.89) v2(50.17,99.11) v2(50.16,24.38) v2(50.16,23.24) v2(50.32,13.36) v2(50.42,15.11) v2(51.18,22.35) v2(51.31,25.27) v2(51.69,12.06) v2(51.69,10.79) v2(52,0.89) v2(52.08,99.11) v2(53.9,0.89) v2(53.98,99.11) v2(54.36,74.93) v2(55.81,0.89) v2(55.89,99.11) v2(57.02,72.77) v2(57.71,0.89) v2(57.79,99.11) v2(59.62,0.89) v2(59.7,99.11) v2(60.76,48.23) v2(61.14,45.75) v2(61.52,0.89) v2(61.6,99.11) v2(63.43,0.89) v2(63.51,99.11) v2(65.33,0.89) v2(65.41,99.11) v2(67.24,0.89) v2(67.32,99.11) v2(67.94,56.9) v2(69.14,0.89) v2(69.22,99.11) v2(69.22,56.9) v2(69.85,66.55) v2(70.2,81.41) v2(71.05,0.89) v2(71.13,99.11) v2(71.5,81.41) v2(72.52,81.41) v2(73.03,99.11) v2(72.95,0.89) v2(74.94,99.11) v2(74.86,0.89) v2(75.69,18.8) v2(76.84,99.11) v2(77.47,49.91) v2(78.49,81.66) v2(78.75,99.11) v2(79.12,9.79) v2(79.5,84.84) v2(79.63,66.41) v2(79.63,8.36) v2(79.76,5.72) v2(80.39,81.84) v2(80.39,8.36) v2(80.65,99.11) v2(80.77,51.05) v2(81.2,9.53) v2(81.66,5.82) v2(82.42,68.73) v2(82.56,99.11) v2(82.8,5.05) v2(84.46,99.11) v2(84.8,81.79) v2(85.6,56.64) v2(86.37,99.11) v2(86.56,61.59) v2(86.87,48.9) v2(87.12,68.33) v2(87.12,58.32) v2(87.5,12.57) v2(87.5,11.68) v2(88.27,99.11) v2(88.39,13.34) v2(88.9,59.05) v2(89.82,58.67) v2(89.79,10.64) v2(90.04,45.34) v2(90.18,99.11) v2(90.3,22.61) v2(90.3,21.84) v2(90.3,21.08) v2(90.3,8.36) v2(90.5,5.37) v2(90.55,68.33) v2(90.68,79.76) v2(90.81,52.73) v2(90.93,19.43) v2(91.06,8.36) v2(91.44,66.67) v2(91.44,65.66) v2(91.44,64.64) v2(91.57,20.45) v2(91.69,75.95) v2(92.08,99.11) v2(92.08,10.55) v2(92.58,16.89) v2(92.71,75.95) v2(93.34,46.61) v2(93.34,8.13) v2(93.47,5.05) v2(93.73,75.95) v2(93.99,99.11) v2(94.49,14.99) v2(94.49,13.46) v2(94.74,38.86) v2(95.63,17.27) v2(95.89,99.11) v2(95.89,43.56) v2(97.16,72.39) v2(97.34,0.89) v2(97.8,99.11) v2(98.17,31.88) v2(98.3,72.39) v2(98.42,53.34) v2(99.7,99.11) v2(99.69,72.39) v2(100.46,58.42) v2(101.61,99.11) v2(101.6,77.72) v2(103.51,99.11) v2(104.39,29.84) v2(104.65,76.33) v2(104.78,36.83) v2(104.78,34.92) v2(105.16,50.04) v2(105.42,99.11) v2(105.79,63.37) v2(106.05,33.66) v2(106.68,36.83) v2(107.06,50.34) v2(107.06,31.75) v2(107.06,30.23) v2(107.06,28.7) v2(107.32,99.11) v2(107.25,75.06) v2(107.31,33.02) v2(107.44,46.77) v2(107.44,45.5) v2(108.71,46.77) v2(108.71,45.5) v2(108.84,31.11) v2(108.84,29.46) v2(108.97,37.34) v2(109.23,99.11) v2(109.98,46.77) v2(109.98,33.02) v2(110.74,36.83) v2(111.13,99.11) v2(111.25,33.02) v2(111.63,31.37) v2(111.63,29.34) v2(112.39,56.77) v2(112.9,32.38) v2(113.04,99.11) v2(113.03,37.34) v2(113.16,30.23) v2(113.92,62.61) v2(114.94,99.11) v2(114.94,56.64) v2(114.94,55.24) v2(116.59,22.35) v2(116.85,99.11) v2(117.09,30.23) v2(118.62,33.15) v2(118.75,99.11) v2(118.87,25.96) v2(119.41,19.68) v2(120.66,99.11) v2(120.65,29.21) v2(121.28,27.94) v2(121.41,24.89) v2(122.48,0.89) v2(122.56,99.11) v2(124.39,0.89) v2(124.47,99.11) v2(124.59,22.23) v2(125.09,59.05) v2(125.09,16.26) v2(125.09,15.24) v2(125.73,52.07) v2(125.73,50.8) v2(125.73,19.3) v2(126.11,20.32) v2(126.29,0.89) v2(126.37,99.11) v2(126.36,24.89) v2(126.36,23.62) v2(127,52.07) v2(127,50.8) v2(127.64,61.59) v2(127.64,60.33) v2(127.64,59.05) v2(127.64,26.16) v2(127.64,24.89) v2(128.2,0.89) v2(128.28,99.11) v2(128.4,64.9) v2(128.91,61.59) v2(129.16,64.9) v2(129.67,13.34) v2(129.92,64.9) v2(130.1,0.89) v2(130.18,99.11) v2(130.56,14.99) v2(132.01,0.89) v2(132.09,99.11) v2(133.35,52.07) v2(133.35,50.8) v2(133.35,38.73) v2(133.35,37.47) v2(133.35,36.2) v2(133.35,34.92) v2(133.91,0.89) v2(133.99,99.11) v2(134.49,17.14) v2(134.62,52.07) v2(134.62,50.8) v2(134.62,39.37) v2(134.62,38.1) v2(134.62,36.83) v2(134.62,35.56) v2(134.62,34.29) v2(134.62,33.02) v2(134.62,31.75) v2(134.62,30.48) v2(134.75,14.99) v2(134.87,22.86) v2(134.87,20.95) v2(135.64,14.99) v2(135.82,0.89) v2(135.9,99.11) v2(135.89,52.07) v2(135.89,50.8) v2(135.89,36.2) v2(135.89,34.92) v2(135.89,33.66) v2(135.89,32.38) v2(135.89,31.11) v2(135.89,29.84) v2(136.7,15.24) v2(137.03,12.83) v2(137.16,52.07) v2(137.16,50.8) v2(137.72,0.89) v2(137.8,99.11) v2(138.43,52.07) v2(138.43,50.8) v2(139.06,39.37) v2(139.06,38.1) v2(139.63,0.89) v2(139.71,99.11) v2(139.7,52.07) v2(139.7,50.8) v2(139.95,82.17) v2(140.34,39.37) v2(140.34,38.1) v2(140.97,52.07) v2(140.97,50.8) v2(141.35,22.61) v2(141.35,19.43) v2(141.53,0.89) v2(141.61,99.11) v2(141.6,23.75) v2(141.86,66.42) v2(141.99,20.19) v2(142.24,52.07) v2(142.24,50.8) v2(142.24,39.37) v2(142.24,38.1) v2(142.62,19.43) v2(142.75,66.42) v2(143.44,0.89) v2(143.52,99.11) v2(143.51,52.07) v2(143.51,50.8) v2(143.51,23.75) v2(144.15,39.37) v2(144.78,52.07) v2(144.78,50.8) v2(145.34,0.89) v2(145.42,99.11) v2(147.25,0.89) v2(147.33,99.11) v2(147.57,19.81) v2(147.9,91.38) v2(148.08,21.21) v2(149.11,98.44) v2(149.11,96.53) v2(149.11,94.63) v2(149.11,92.72) v2(149.11,90.82) v2(149.11,88.91) v2(149.11,87.01) v2(149.11,85.1) v2(149.11,83.2) v2(149.11,81.29) v2(149.11,79.39) v2(149.11,66.05) v2(149.11,64.15) v2(149.11,62.24) v2(149.11,60.34) v2(149.11,58.43) v2(149.11,56.53) v2(149.11,54.62) v2(149.11,52.72) v2(149.11,50.81) v2(149.11,48.91) v2(149.11,47) v2(149.11,45.1) v2(149.11,43.19) v2(149.11,41.29) v2(149.11,39.38) v2(149.11,37.48) v2(149.11,26.05) v2(149.11,24.14) v2(149.11,22.24) v2(149.11,20.33) v2(149.11,18.43) v2(149.11,16.52) v2(149.11,14.62) v2(149.11,12.71) v2(149.11,10.81) v2(149.11,8.9) v2(149.11,7) v2(149.11,5.09) v2(149.11,3.19) v2(149.11,1.28)
